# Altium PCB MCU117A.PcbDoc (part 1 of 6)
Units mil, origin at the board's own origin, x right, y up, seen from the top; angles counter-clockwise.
Board outline 2300 x 6749.64 mil, 6 copper layers (Top Signal, GND, Middle Signal, PWR, GND2, Bottom Signal), stack 61.64 mil thick; 424 components, 343 nets, 1563 pads, 921 vias.
Unrouted connection lines stored in the file: 4.
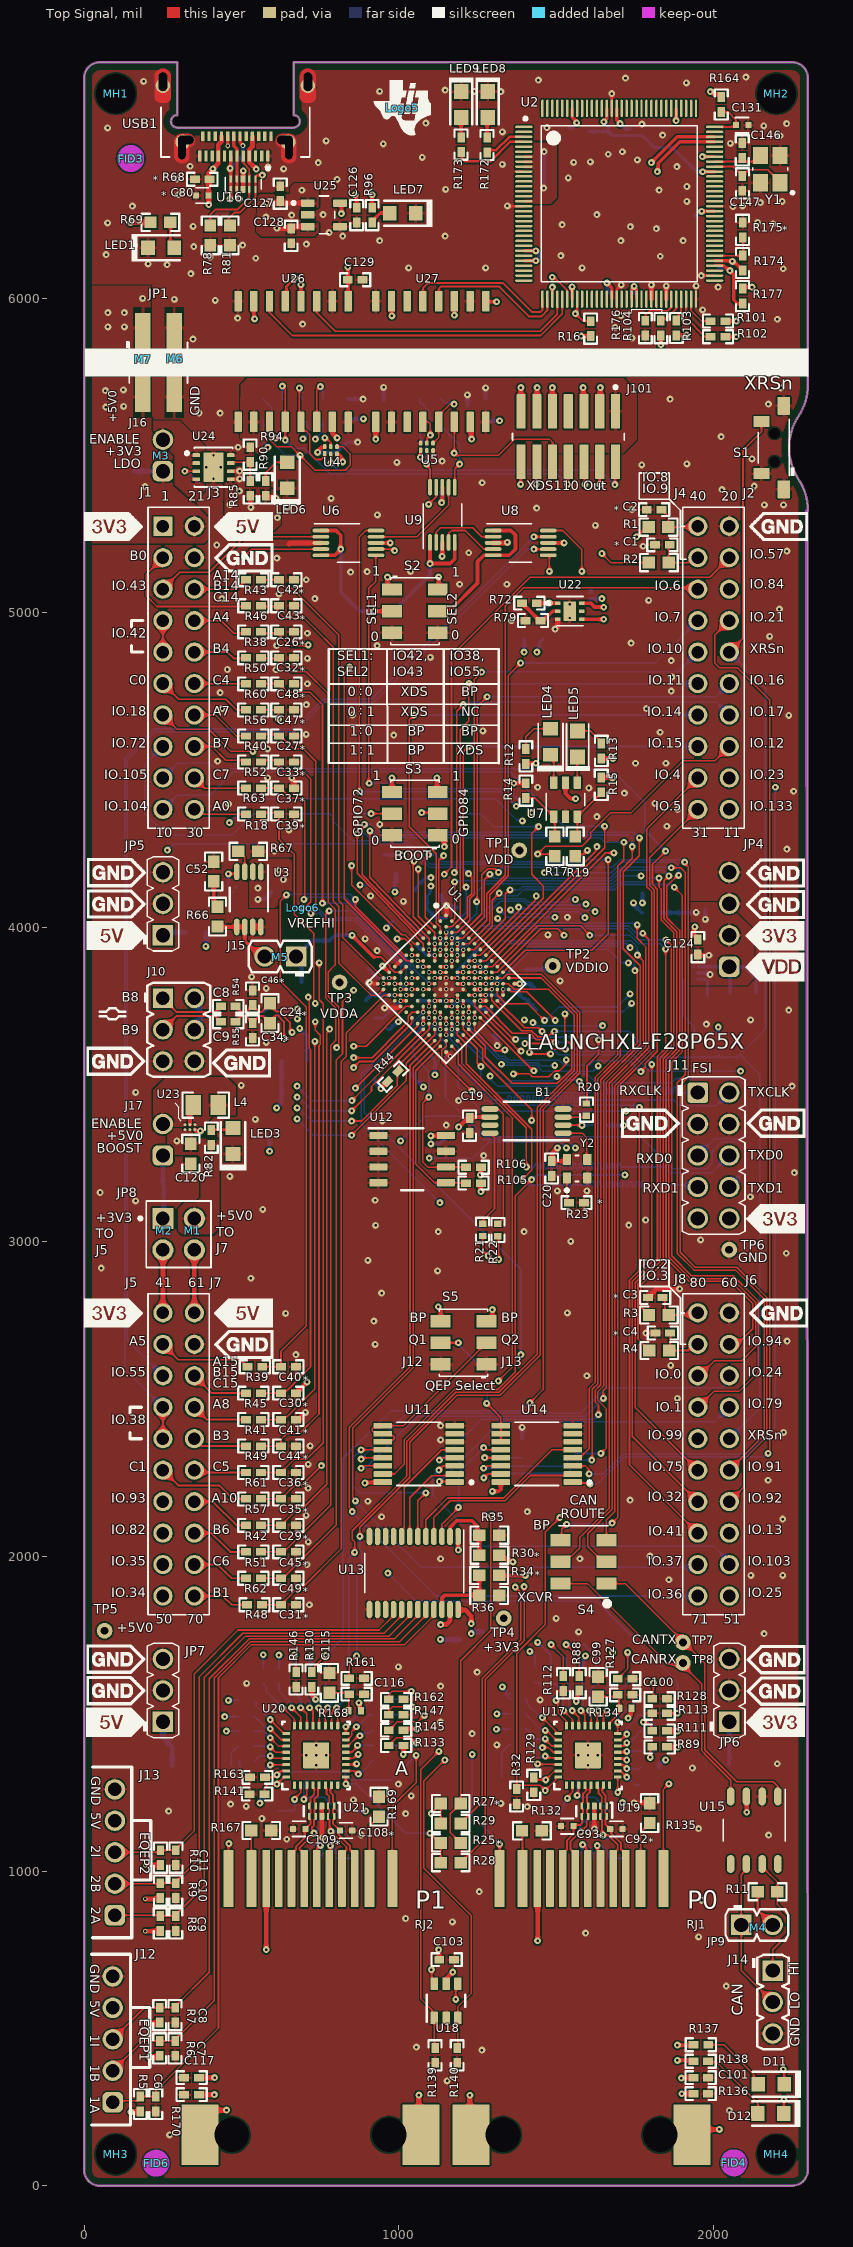
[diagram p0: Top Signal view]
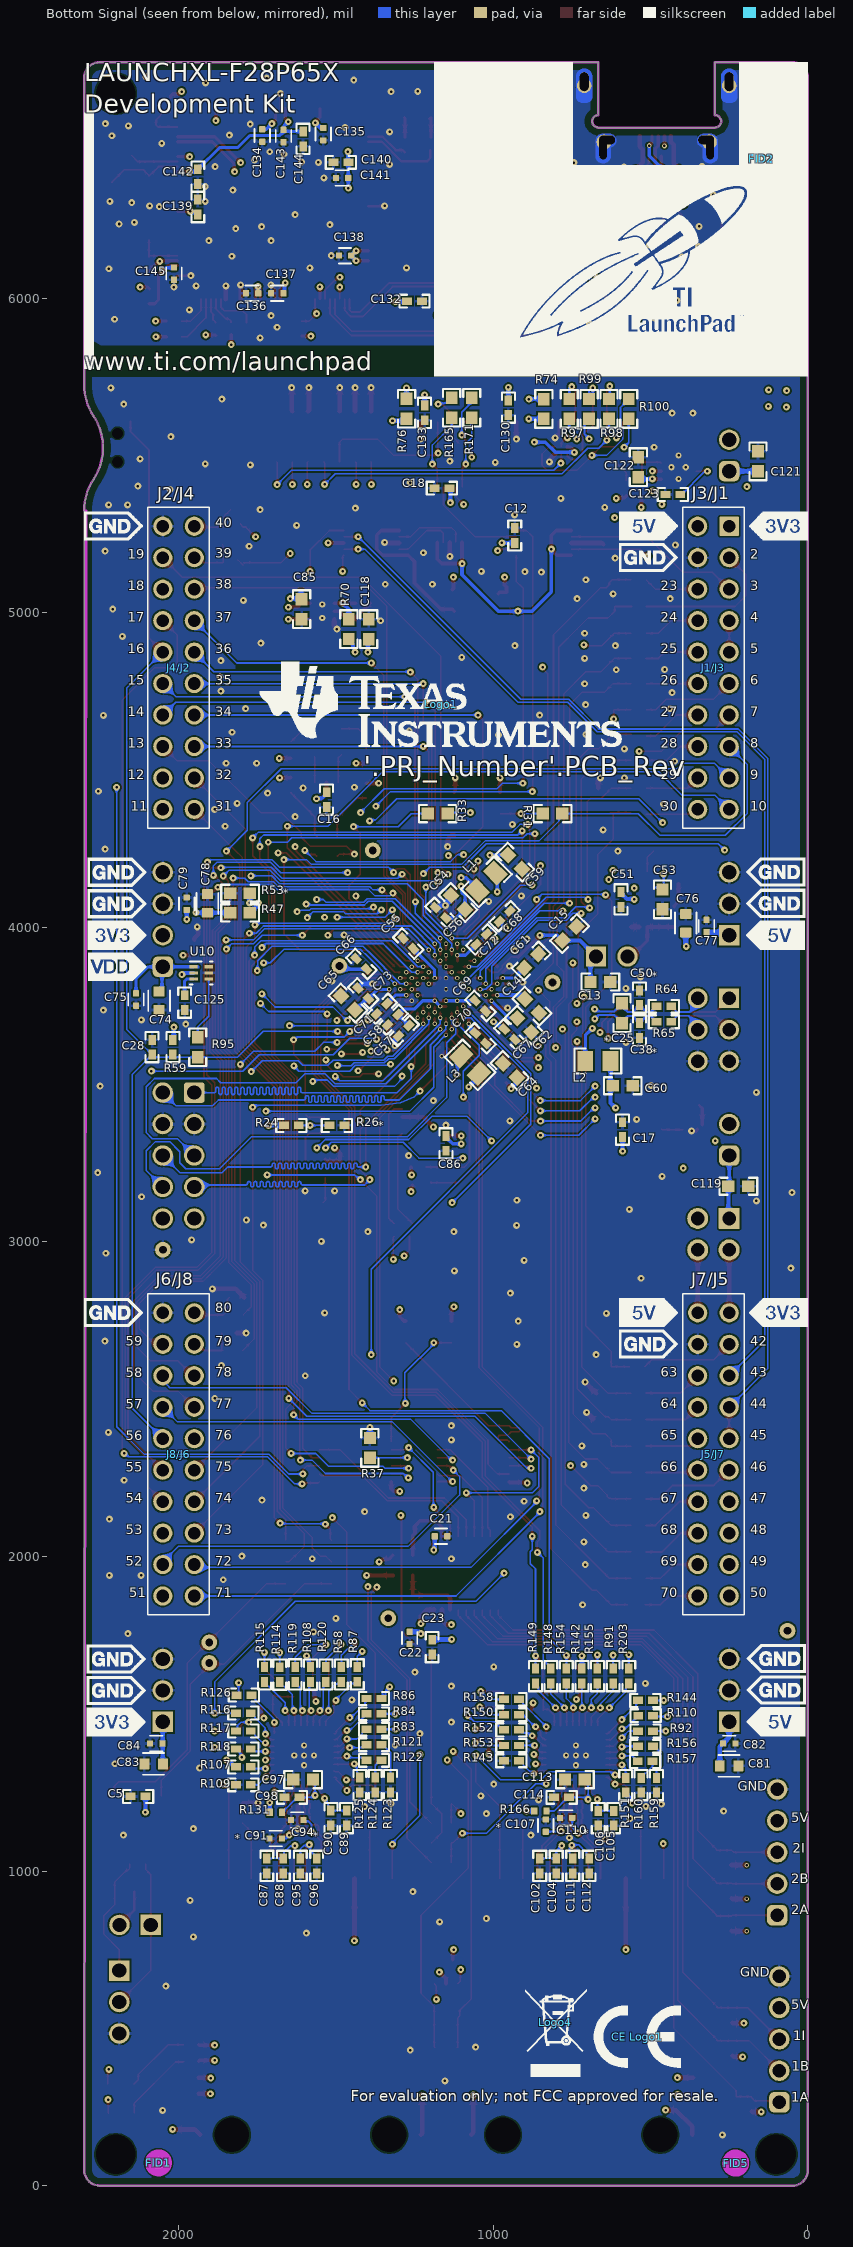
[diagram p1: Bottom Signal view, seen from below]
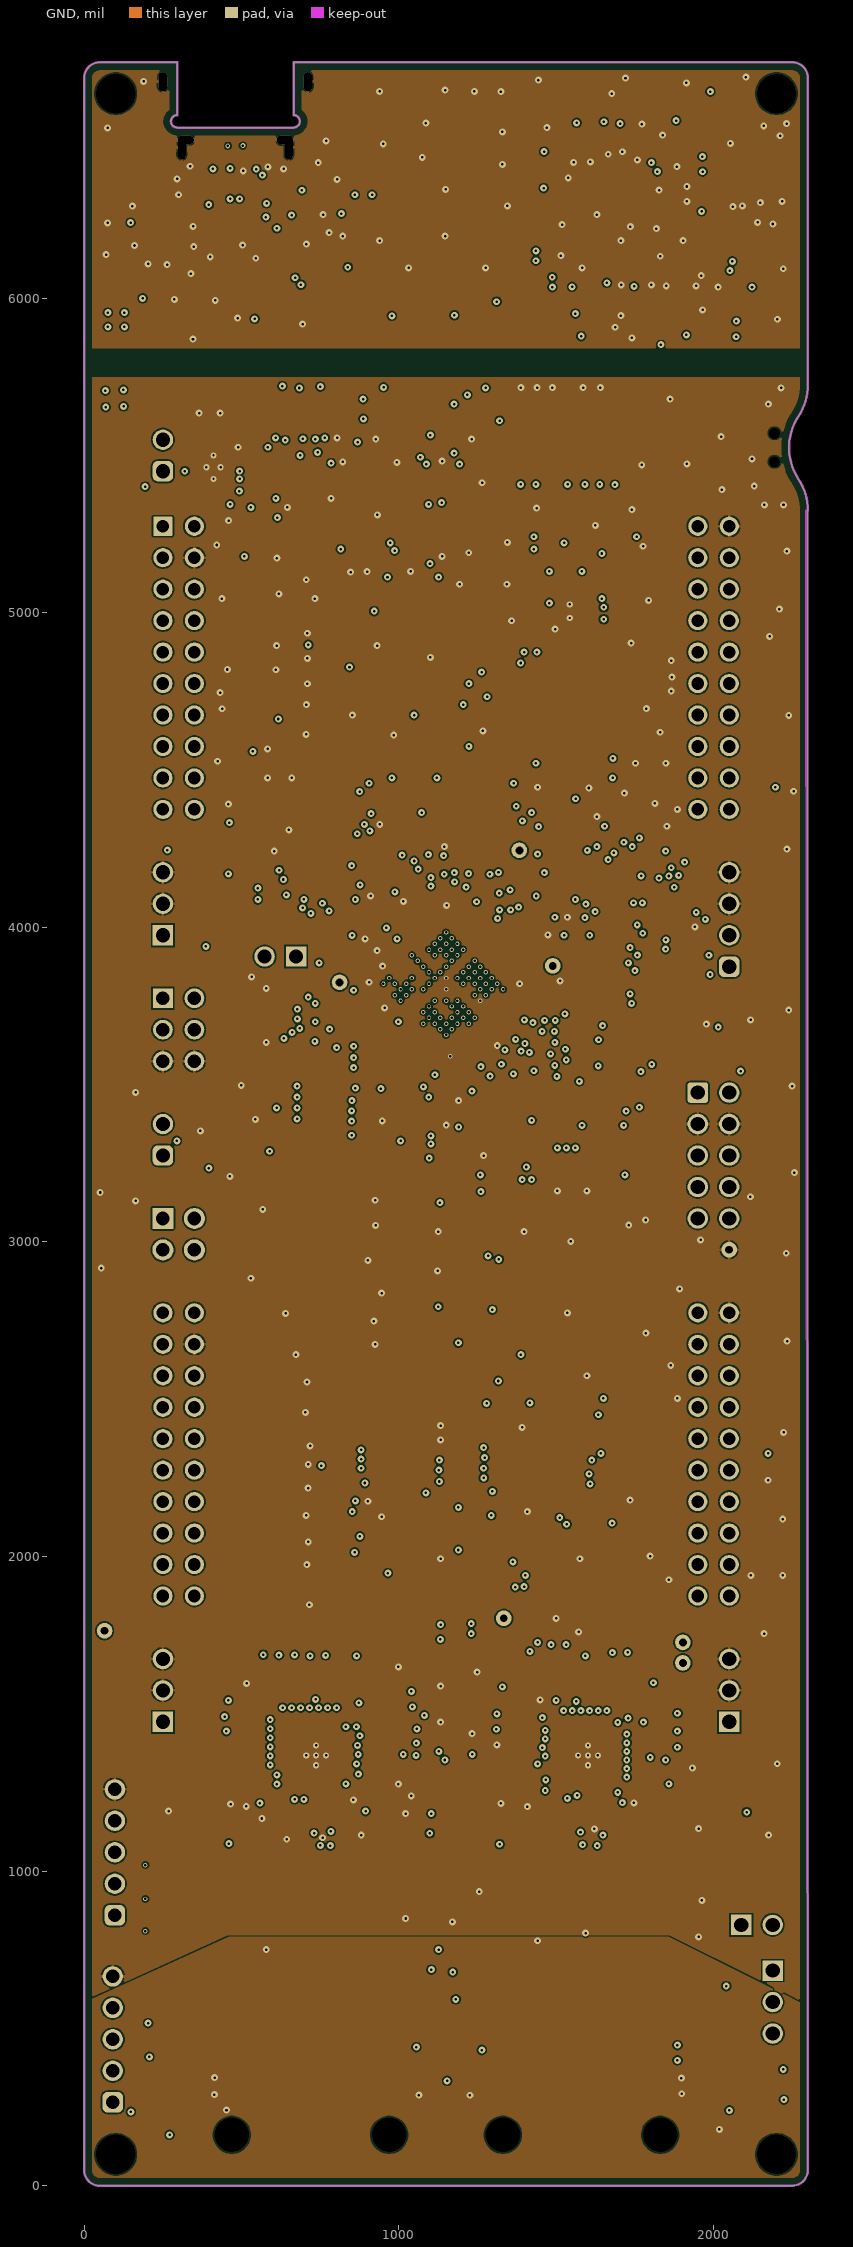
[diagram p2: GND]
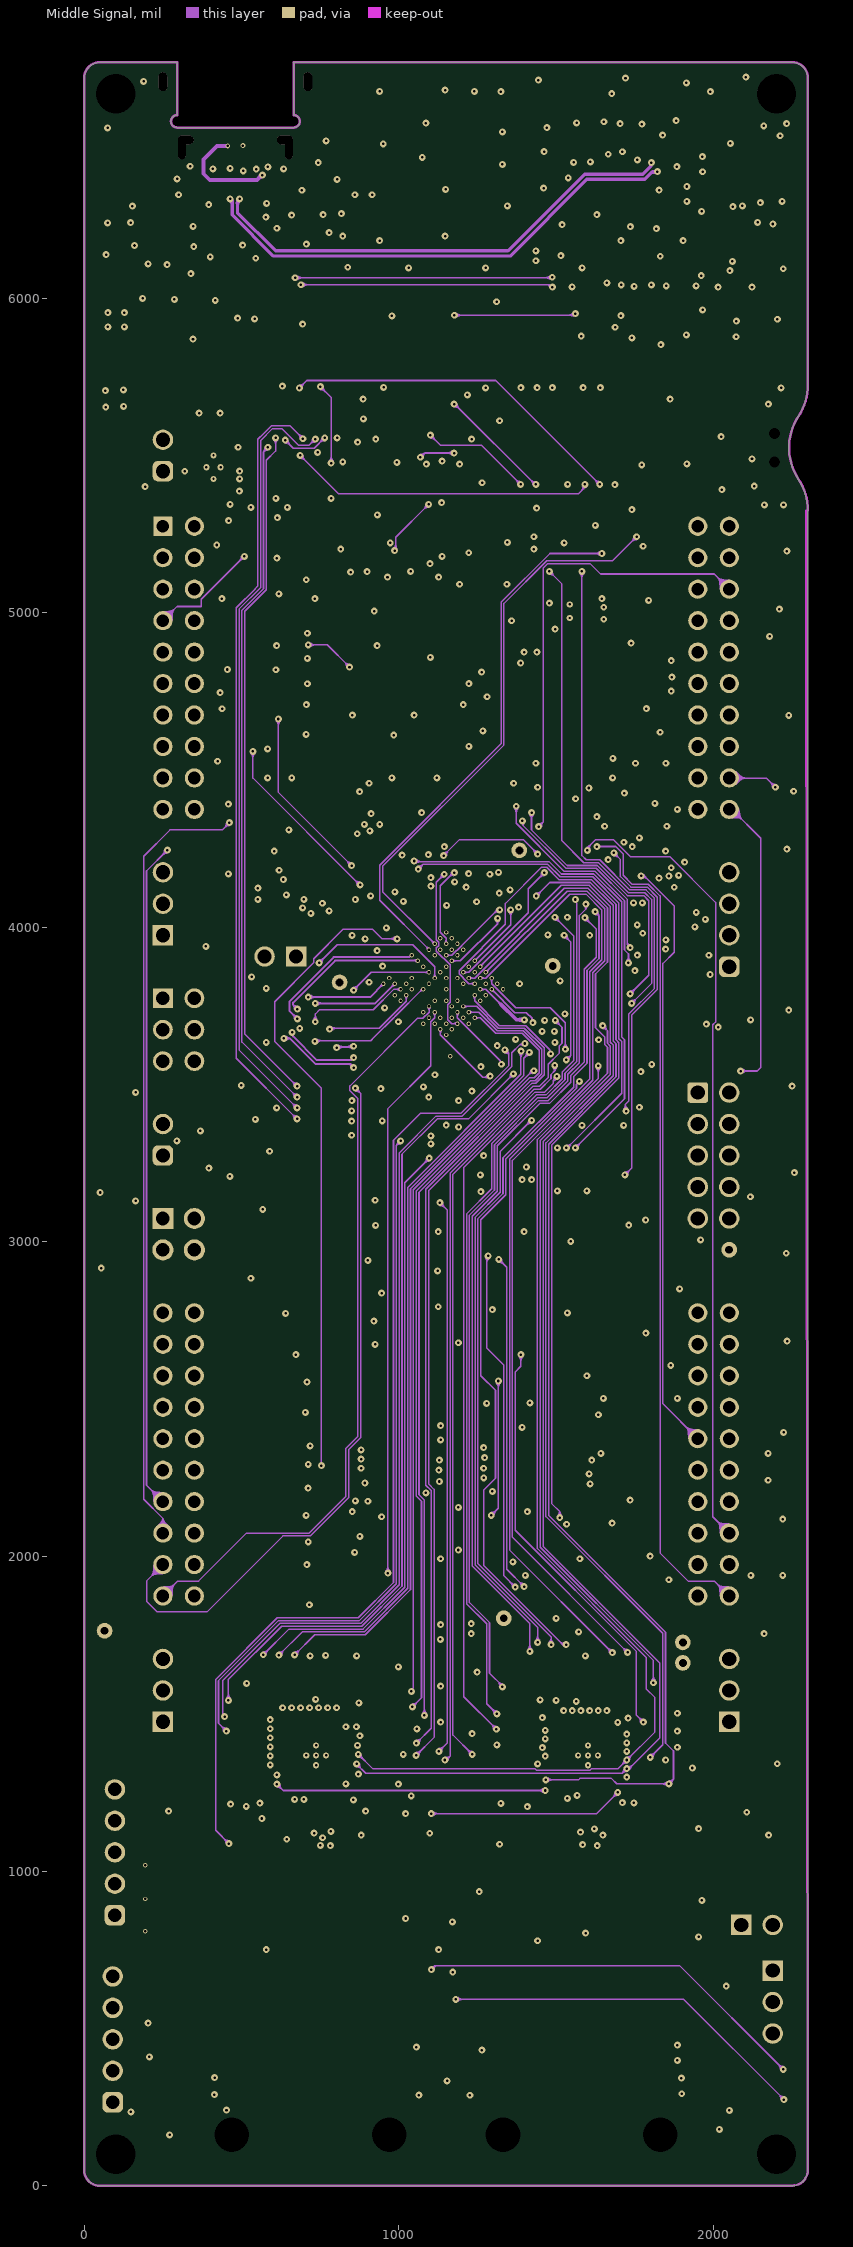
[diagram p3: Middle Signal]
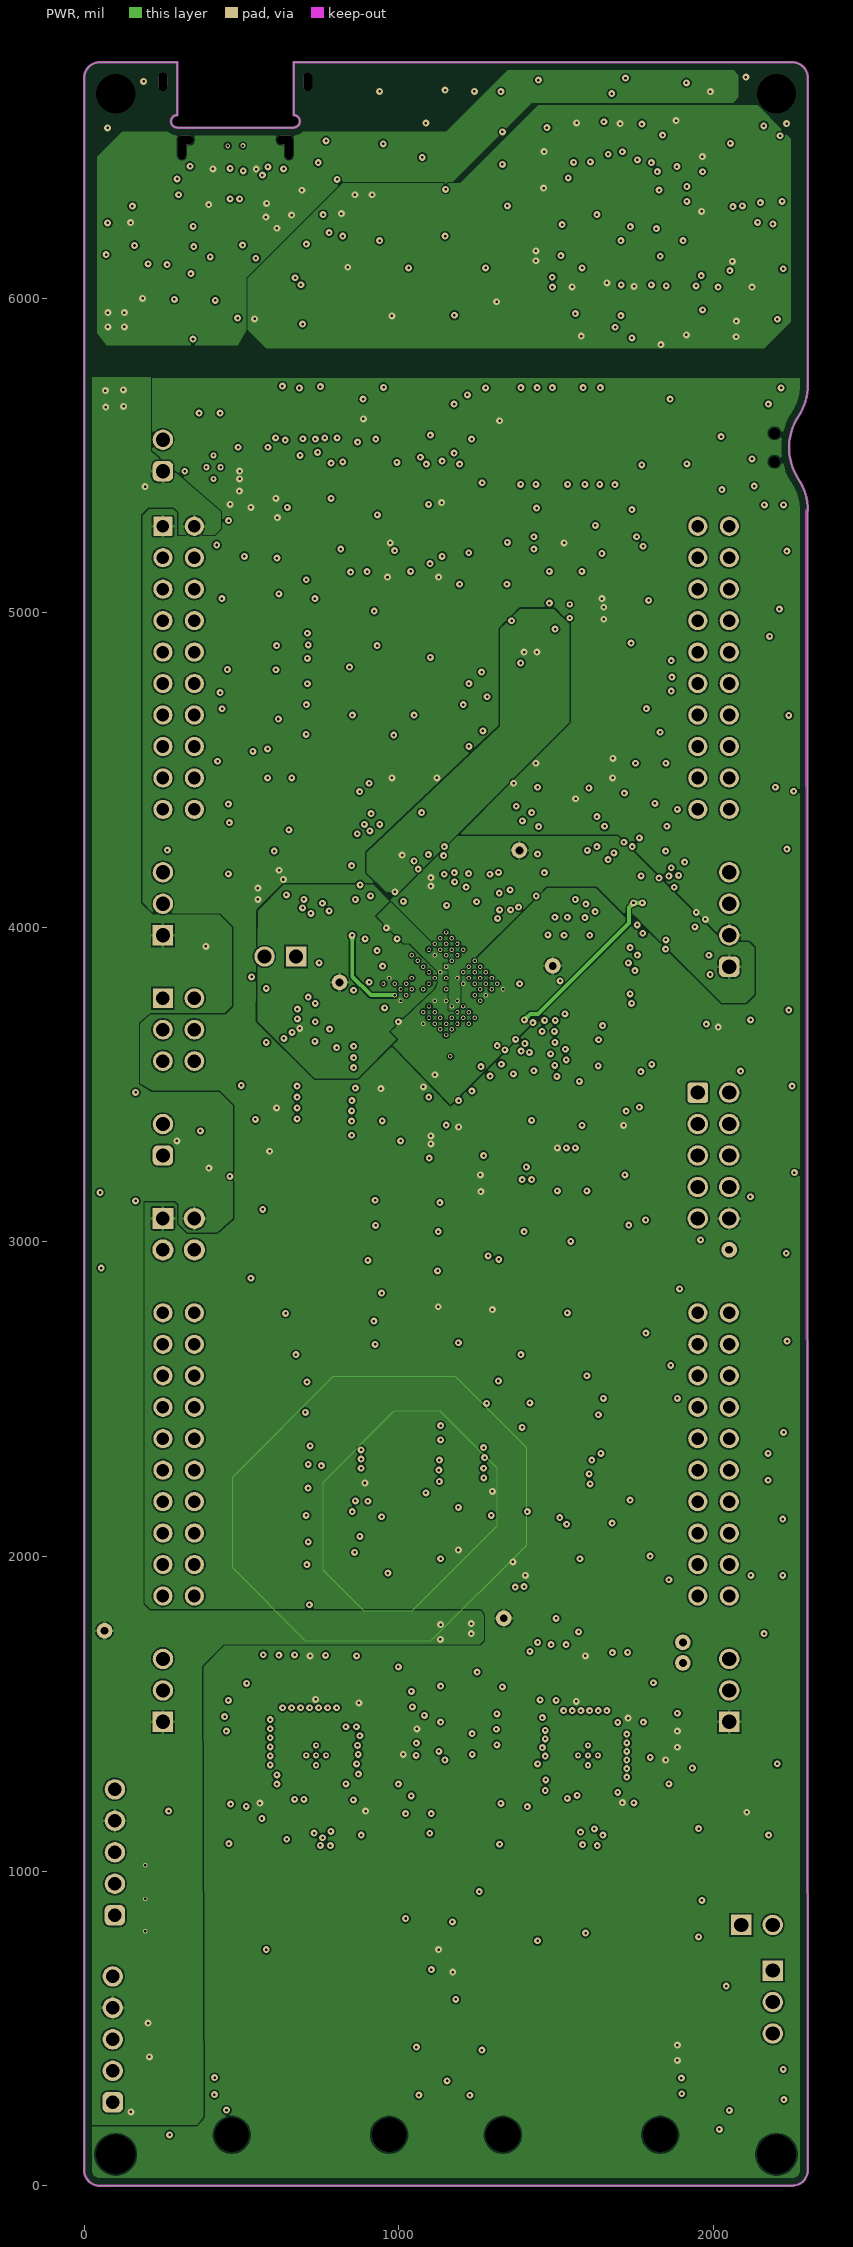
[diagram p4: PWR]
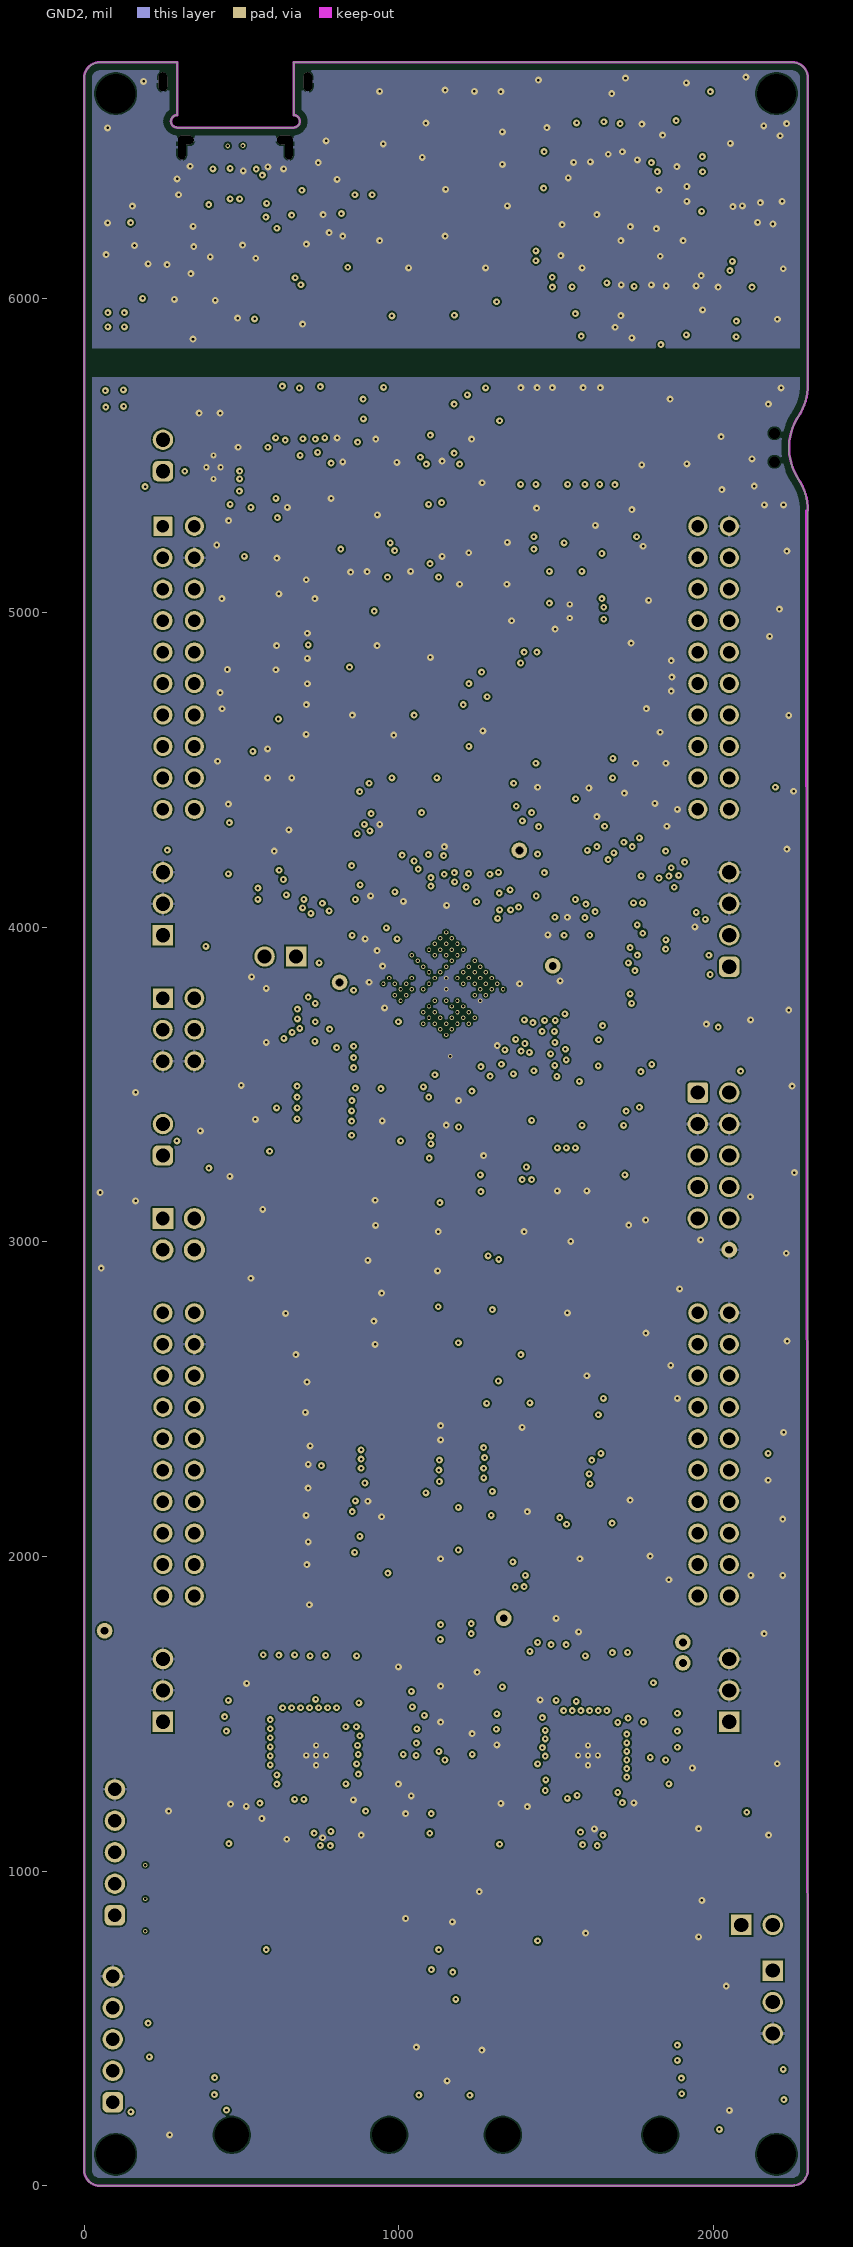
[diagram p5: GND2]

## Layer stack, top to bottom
Top Solder: solder mask 0.4, Solder Resist, Dk 3.5
Top Signal: signal copper 1.4
Dielectric 1: prepreg 6.25, FR-4, Dk 4.2
GND: signal copper 1.4
Dielectric 2: core 16.1, FR-4, Dk 4.2
Middle Signal: signal copper 1.4
Dielectric 3: prepreg 8.54, FR-4, Dk 4.2
PWR: signal copper 1.4
Dielectric 4: core 16.1, FR-4, Dk 4.2
GND2: signal copper 1.4
Dielectric 5: prepreg 6.25, FR-4, Dk 4.2
Bottom Signal: signal copper 1.4
Bottom Solder: solder mask 0.4, Solder Resist, Dk 3.5

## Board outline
49.64,0 cw(c49.64,50) -0.36,50 -0.36,6699 cw(c49.64,6699) 49.64,6749 294.91,6749 295.27,6749.64 295.27,6581.14 ccw(c295.27,6561.46) 275.58,6561.46 ccw(c295.27,6561.46) 295.27,6541.77 665.35,6541.77 ccw(c665.35,6561.46) 685.03,6561.46 ccw(c665.35,6561.46) 665.35,6581.14 665.35,6749.64 664.99,6749 2249.64,6749 cw(c2249.64,6699) 2299.64,6699 2299.64,5724 cw(c2117.97,5724) 2269.64,5624 ccw(c2421.3,5524) 2269.64,5424 cw(c2117.97,5324) 2299.64,5324 2299.64,50 cw(c2249.64,50) 2249.64,0

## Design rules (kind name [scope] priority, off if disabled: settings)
AcuteAngle [All] p1: minimum=4.50000000000000E+0001 checktracksonly=TRUE
AcuteAngle AcuteAngle_poly [InPolygon] p2: minimum=4.50000000000000E+0001 checktracksonly=FALSE
AssemblyTestPointUsage [All] p1: valid=2
BoardOutlineClearance BoardOutlineClearance_USB1 [InComponent('USB1')] p1: gap=0 ignorepadtopadclearanceinfootprint=FALSE
BoardOutlineClearance BoardOutlineClearance_MountingHoles [OnCopper and InComponentClass('Mounting Holes')] p2: gap=40 ignorepadtopadclearanceinfootprint=FALSE
BoardOutlineClearance BoardOutlineClearance_Poly [OnCopper and IsPoly] p3: gap=25 ignorepadtopadclearanceinfootprint=FALSE
BoardOutlineClearance [OnCopper and Not InComponentClass('Logo') and not InComponentClass('FiducialMark') and not InRegion(1000,500,4000,800) and not InPoly] p4: gap=10 ignorepadtopadclearanceinfootprint=FALSE
Clearance Poly [InPolygon] p1: gap=5 ignorepadtopadclearanceinfootprint=FALSE
Clearance "RJ45 pad" [InComponent('RJ1') OR InComponent('RJ2')] p2: gap=5 ignorepadtopadclearanceinfootprint=TRUE except(0: SMDPad-THPad)
Clearance Keepout [((IsTrack Or IsArc) And Not InPoly) And IsFree and IsKeepOut vs ((IsTrack Or IsArc) And Not InPoly) And IsFree and IsKeepOut] p3: gap=5 ignorepadtopadclearanceinfootprint=FALSE
Clearance USB1 [InComponent('USB1') vs OnLayer('Keep-Out Layer')] p4: gap=7.87 ignorepadtopadclearanceinfootprint=FALSE
Clearance ISVIA [ISVIA vs ISVIA] p5: gap=0.2 ignorepadtopadclearanceinfootprint=FALSE
Clearance Clearance_FiducialMark [IsKeepOut and InComponentClass('FiducialMark') vs IsPad and InComponentClass('FiducialMark')] p6: gap=0 ignorepadtopadclearanceinfootprint=FALSE
Clearance Clearance_Boardedge [All vs IsKeepOut] p7: gap=11.81 ignorepadtopadclearanceinfootprint=FALSE
Clearance INPOLYGON [InPolygon] p8: gap=11.91 ignorepadtopadclearanceinfootprint=FALSE
Clearance [All] p9: gap=5 ignorepadtopadclearanceinfootprint=FALSE except(3.7: Arc-Via Track-Via; 4: Arc-Arc Arc-Track Arc-SMDPad Track-Track Track-SMDPad)
ComponentClearance "ComponentClearance_overlay to overlay" [OnBottomSilkscreen vs OnTopSilkscreen] p1: gap=0 collisioncheckmode=3 verticalgap=0 showdistances=FALSE
ComponentClearance ComponentClearance_MountingHoles_FiducialMarks [InComponentClass('Mounting Holes') vs InComponentClass('FiducialMark')] p2: gap=10 collisioncheckmode=3 verticalgap=10 showdistances=FALSE
ComponentClearance ComponentClearance_Shunt [InComponentClass('Header') vs InComponentClass('Shunt')] p3: gap=0 collisioncheckmode=3 verticalgap=0 showdistances=FALSE
ComponentClearance ComponentClearance_Logo [InComponentClass('Logo')] p4: gap=10 collisioncheckmode=3 verticalgap=10 showdistances=FALSE
ComponentClearance ComponentClearance_ScrewToNut [(HasFootprint('NY PMS 440 0025 PH')) vs (HasFootprint('Keystone_1902C'))] p5: gap=5 collisioncheckmode=3 verticalgap=10 showdistances=FALSE
ComponentClearance ComponentClearance_MountingHoles [InComponentClass('Mounting Holes')] p6 off: gap=250 collisioncheckmode=3 verticalgap=100000 showdistances=FALSE
ComponentClearance ComponentClearance_SmallPassives [HasFootprint('0201*') or HasFootprint('0402*') or HasFootprint('0508') or HasFootprint('0603*') or HasFootprint('0612') or HasFootprint('0805*') or HasFootprint('0815*') or HasFootprint('0830*') or HasFootprint('1206*') or HasFootprint('1210*') or HasFootprint('1808*') or HasFootprint('1812*') or HasFootprint('1825*') or HasFootprint('2010*') or HasFootprint('2220*') or HasFootprint('2225*') or HasFootprint('2512*') or HasFootprint('2728*') or HasFootprint('3518*') vs HasFootprint('0201*') or HasFootprint('0402*') or HasFootprint('0508') or HasFootprint('0603*') or HasFootprint('0612') or HasFootprint('0805*') or HasFootprint('0815*') or HasFootprint('0830*') or HasFootprint('1206*') or HasFootprint('1210*') or HasFootprint('1808*') or HasFootprint('1812*') or HasFootprint('1825*') or HasFootprint('2010*') or HasFootprint('2220*') or HasFootprint('2225*') or HasFootprint('2512*') or HasFootprint('2728*') or HasFootprint('3518*')] p7 off: gap=10 collisioncheckmode=3 verticalgap=0 showdistances=FALSE
ComponentClearance ComponentClearance_THtoSMT [IsThruComponent vs IsSMTComponent] p8 off: gap=30 collisioncheckmode=3 verticalgap=30 showdistances=FALSE
ComponentClearance ComponentClearance_THtoTH [IsThruComponent vs IsThruComponent] p9 off: gap=30 collisioncheckmode=3 verticalgap=30 showdistances=FALSE
DiffPairsRouting USB_DiffPairsRouting_90 [InDifferentialPairClass('All Differential Pairs')] p1: maxlimit=100 minlimit=5 mostfreqgap=6 toplayer_minwidth=4 toplayer_maxwidth=15 toplayer_prefwidth=6.1 midlayer1_minwidth=6 midlayer1_maxwidth=15 midlayer1_prefwidth=6.1 midlayer2_minwidth=6 midlayer2_maxwidth=15 midlayer2_prefwidth=6.1 midlayer3_minwidth=6 midlayer3_maxwidth=15 midlayer3_prefwidth=6.1 midlayer4_minwidth=6 midlayer4_maxwidth=15 midlayer4_prefwidth=6.1 bottomlayer_minwidth=4 bottomlayer_maxwidth=15 bottomlayer_prefwidth=6.1 maxuncoupledlength=1000
DiffPairsRouting [All] p2: maxlimit=10 minlimit=6 mostfreqgap=6 toplayer_minwidth=4 toplayer_maxwidth=6.2 toplayer_prefwidth=4.9 midlayer1_minwidth=4.9 midlayer1_maxwidth=6.2 midlayer1_prefwidth=4.9 midlayer2_minwidth=4.9 midlayer2_maxwidth=15 midlayer2_prefwidth=4.9 midlayer3_minwidth=4.9 midlayer3_maxwidth=15 midlayer3_prefwidth=4.9 midlayer4_minwidth=4.9 midlayer4_maxwidth=15 midlayer4_prefwidth=4.9 bottomlayer_minwidth=4 bottomlayer_maxwidth=6.2 bottomlayer_prefwidth=4.9 maxuncoupledlength=500
FabricationTestPointUsage TestPointUsage [All] p1: valid=2 allowmultiple=FALSE
FabricationTestpoint Testpoint [All] p1: side=3 testpointundercomponent=TRUE minsize=40 maxsize=100 preferedsize=60 minholesize=0 maxholesize=40 preferedholesize=32 testpointgrid=1 allowsidetop=TRUE allowsidebottom=TRUE usegrid=TRUE gridtolerance=0.01
FanoutControl Fanout_LCC [IsLCC] p1: bgadir=Out bgaviamode=Centered fanoutstyle=Auto fanoutdirection=Alternating viagrid=1 // Fanout_LCC (Default Rule)
FanoutControl Fanout_BGA [IsBGA] p2: bgadir=Out bgaviamode=Centered fanoutstyle=Auto fanoutdirection=Alternating viagrid=1 // Fanout_BGA (Default Rule)
FanoutControl Fanout_Default [All] p4: bgadir=Out bgaviamode=Centered fanoutstyle=Auto fanoutdirection=Alternating viagrid=1 // Fanout_Default (Default Rule)
FanoutControl Fanout_Small [(CompPinCount < 5)] p5: bgadir=Out bgaviamode=Centered fanoutstyle=Auto fanoutdirection=OutThenIn viagrid=1 // Fanout_Small (Default Rule)
HoleSize [All] p1: absolutevalues=TRUE maxlimit=251 minlimit=7.87 maxpercent=80.000 minpercent=20.000
HoleToHoleClearance HoleToHoleClearance_USB1 [InComponent('USB1') vs InComponent('USB1')] p1: gap=0 allowstackedmicrovias=TRUE
HoleToHoleClearance [All] p2: gap=10 allowstackedmicrovias=TRUE
MatchedLengths FSIRX [InNetClass('FSIRX')] p1: tolerance=25 checknetsindiffpair=FALSE checkdiffpairvsdiffpair=TRUE checkxsignals=TRUE checkothers=TRUE
MatchedLengths FSITX [InNetClass('FSITX')] p2: tolerance=25 checknetsindiffpair=FALSE checkdiffpairvsdiffpair=TRUE checkxsignals=TRUE checkothers=TRUE
MinimumAnnularRing MinimumAnnularRing_ThermalPadVias [IsVia and InAnyComponent] p1: minimumring=3
MinimumAnnularRing MinimumAnnularRing_usb1 [InComponent('USB1')] p2: minimumring=0
MinimumAnnularRing [All] p3: minimumring=3
MinimumSolderMaskSliver MinimumSolderMaskSliver_Logo [InComponentClass('Logo') vs InComponentClass('Logo')] p1: minsoldermaskwidth=0.7
MinimumSolderMaskSliver [All] p2: minsoldermaskwidth=3
PlaneClearance PlaneClearance_Via [IsVia] p1: clearance=10
PlaneClearance [All] p2: clearance=10
PlaneConnect [All] p1: planeconnectstyle=Relief reliefexpansion=10 reliefentries=4 reliefconductorwidth=25 reliefairgap=10
PolygonConnect PolygonConnect_via [IsVia] p1: connectstyle=Direct reliefconductorwidth=10 reliefentries=4 polygonreliefangle="90 Angle" airgapwidth=10
PolygonConnect PolygonConnect_GND_under_device [Name = 'TOP_SIGNAL_GND_P125'] p2: connectstyle=Direct reliefconductorwidth=10 reliefentries=4 polygonreliefangle="90 Angle" airgapwidth=5
PolygonConnect PolygonConnect_via_VDD [Name = 'PWR_VDD_P012'] p3: thpad.connectstyle=Relief thpad.reliefconductorwidth=10 thpad.reliefentries=4 thpad.polygonreliefangle="90 Angle" thpad.airgapwidth=5 smdpad.connectstyle=Relief smdpad.reliefconductorwidth=10 smdpad.reliefentries=4 smdpad.polygonreliefangle="90 Angle" smdpad.airgapwidth=5 via.connectstyle=Direct via.reliefconductorwidth=10 via.reliefentries=4 via.polygonreliefangle="90 Angle" via.airgapwidth=5
PolygonConnect PolygonConnect_via_VDDIO [Name = 'PWR_VDDIO_P129'] p4: thpad.connectstyle=Relief thpad.reliefconductorwidth=10 thpad.reliefentries=4 thpad.polygonreliefangle="90 Angle" thpad.airgapwidth=5 smdpad.connectstyle=Relief smdpad.reliefconductorwidth=10 smdpad.reliefentries=4 smdpad.polygonreliefangle="90 Angle" smdpad.airgapwidth=5 via.connectstyle=Direct via.reliefconductorwidth=10 via.reliefentries=4 via.polygonreliefangle="90 Angle" via.airgapwidth=5
PolygonConnect [All] p5: connectstyle=Relief reliefconductorwidth=10 reliefentries=4 polygonreliefangle="90 Angle" airgapwidth=5
RoutingVias ThermalPadVias [IsVia and InAnyComponent] p1: holewidth=8 width=22 viastyle="Through Hole" minholewidth=7.87 minwidth=14 maxholewidth=8 maxwidth=22
RoutingVias [All] p2: holewidth=8 width=22 viastyle="Through Hole" minholewidth=7.87 minwidth=14 maxholewidth=8 maxwidth=22
ShortCircuit ShortCircuit_RJ45 [InComponent('RJ1') And IsThruPin Or InComponent('RJ2') And IsThruPin] p1: allowed=TRUE
ShortCircuit [All] p2: allowed=FALSE
SilkToBoardRegionClearance [Not ((IsComment or IsDesignator) And (Hide <> 'False')) and not InRegion(1000,500,4000,800)] p1:
SilkToSilkClearance SilkToSilkClearance_Pb-FreeLogo [(HasFootprint('Pb-Free_Overlay_Medium') OR HasFootprint('Pb-Free_Overlay_Small')) vs (HasFootprint('Pb-Free_Overlay_Medium') OR HasFootprint('Pb-Free_Overlay_Small'))] p1: silktosilkclearance=0
SilkToSilkClearance [All] p2: silktosilkclearance=3
SilkToSolderMaskClearance SilkToComponentPadClearance [(IsPad or IsFill or IsRegion) and InAnycomponent] p1: minsilkscreentomaskgap=3 clearancetoexposedcopper=TRUE
SilkToSolderMaskClearance "Silk to Solder Mask Opening" [All] p2: minsilkscreentomaskgap=3 clearancetoexposedcopper=TRUE
SolderMaskExpansion [All] p1: expansion=1.97 istentingtop=FALSE
UnRoutedNet [All] p1: checkbadconnections=TRUE
Width USB_width [InNetClass('Analog')] p1: maxlimit=6.1 minlimit=4 preferedwidth=6
Width [All] p2: maxlimit=15 minlimit=4 preferedwidth=5 checkconnectedcopper=TRUE
11 further rules are at their usual default settings.

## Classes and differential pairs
component class MCU117A_F28P65X_Device: C28 C54 C55 C56 C57 C58 C59 C60 C61 C62 C64 C65 C66 C67 C68 C69 C70 C71 C72 C73 L1 L2 L3 R44 R47 R53 R59 S1
component class MCU117A_XDS110_MCU: C129 C130 C131 C132 C133 C134 C135 C136 C137 C138 C139 C140 C141 C142 C143 C144 C145 C146 C147 J101 LED8 LED9 R16 R74 R76 R97 R98 R99 R100 R101 R102 R103 R104 R164 R165 R171 R172 R173 R174 R175 R176 R177 U2 U4 U5 U26 U27 Y1
component class MCU117A_EtherCAT: C86 C87 C88 C89 C90 C91 C92 C93 C94 C95 C96 C97 C98 C99 C100 C101 C102 C103 C104 C105 C106 C107 C108 C109 C110 C111 C112 C113 C114 C115 C116 C117 D11 D12 R32 R58 R83 R84 R86 R87 R88 R89 R91 R92 R105 R106 R107 R108 R109 R110 R111 R112 R113 R114 R115 R116 R117 R118 R119 R120 R121 R122 R123 R124 R125 R126 R127 R128 R129 R130 R131 R132 R133 R134 R135 R136 R137 R138 R139 R140 R141 R142 R143 R144 R145 R146 R147 R148 R149 R150 R151 R152 R153 R154 R155 R156 R157 R158 R159 R160 R161 R162 R163 R166 R167 R168 R169 R170 R203 RJ1 RJ2 U12 U17 U18 U19 U20 U21
net class FSITX: GPIO49_FSITXD0 GPIO50_FSITXD1 GPIO51_FSITXCLK
net class FSIRX: GPIO52_FSIRXD0 GPIO53_FSIRXD1 GPIO54_FSIRXCLK
component class MCU117A_USB_and_Power: C74 C75 C76 C77 C78 C79 C80 C81 C82 C83 C84 C85 C118 C119 C120 C121 C122 C123 C124 C125 C126 C127 C128 J16 J17 JP1 JP4 JP5 JP6 JP7 JP10 L4 LED1 LED3 LED6 LED7 M5 M6 M7 R68 R69 R70 R72 R78 R79 R81 R82 R85 R90 R94 R95 R96 TP1 TP2 TP3 TP4 TP5 TP6 U10 U16 U22 U23 U24 U25 USB1
component class MCU117A_ADC: C13 C14 C15 C24 C25 C26 C27 C29 C30 C31 C32 C33 C34 C35 C36 C37 C38 C39 C40 C41 C42 C43 C44 C45 C46 C47 C48 C49 C50 C51 C52 C53 J15 M4 R18 R38 R39 R40 R41 R42 R43 R45 R46 R48 R49 R50 R51 R52 R54 R55 R56 R57 R60 R61 R62 R63 R64 R65 R66 R67 R? U1 U3
component class MCU117A_Connectors: C1 C2 C3 C4 C5 C6 C7 C8 C9 C10 C11 J1/J3 J4/J2 J5/J7 J8/J6 J10 J11 J12 J13 J14 JP8 JP9 M1 M2 M3 R1 R2 R3 R4 R5 R6 R7 R8 R9 R10 R11 TP7 TP8 U15
component class MCU117A_AltRouting_Misc: B1 C12 C16 C17 C18 C19 C20 C21 C22 C23 LED4 LED5 R12 R13 R14 R15 R17 R19 R20 R21 R22 R23 R24 R25 R26 R27 R28 R29 R30 R31 R33 R34 R35 R36 R37 S2 S3 S4 S5 U6 U7 U8 U9 U11 U13 U14 Y2
component class Header: J10 J11 J12 J13 J14 J15 J16 J17 JP1 JP4 JP5 JP6 JP7 JP9 JP10
component class AssemblyNote: ZZ1 ZZ2 ZZ3
component class FiducialMark: FID1 FID2 FID3 FID4 FID5 FID6
component class MCU117A_Hardware: "CE Logo1" FID1 FID2 FID3 FID4 FID5 FID6 Logo1 Logo3 Logo4 Logo5 Logo6 MH1 MH2 MH3 MH4 ZZ1 ZZ2 ZZ3
component class Logo: Logo1 Logo5 Logo6
component class Shunt: M1 M2 M3 M4 M5 M6 M7
differential pair MCU_C8C9: +MCU_C8C9_P -MCU_C8C9_N
differential pair ADCINC8C9: +ADCINC8C9_P -ADCINC8C9_N
differential pair MCU_B8B9: +MCU_B8B9_P -MCU_B8B9_N
differential pair USB_D: +USB_D_P -USB_D_N
differential pair ADCINB8B9: +ADCINB8B9_P -ADCINB8B9_N
differential pair PHY1_TD: +PHY1_TD_P -PHY1_TD_N
differential pair PHY1_RD: +PHY1_RD_P -PHY1_RD_N
differential pair PHY0_TD: +PHY0_TD_P -PHY0_TD_N
differential pair PHY0_RD: +PHY0_RD_P -PHY0_RD_N

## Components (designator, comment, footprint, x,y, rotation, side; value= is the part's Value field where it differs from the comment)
B1 "LMK1C1104PW" PW0008A_N 1405.4,3384.12 r180 top
C1 "885012205037" 0402 1837.29,5215.41 r180 top value=0.1uF
C2 "885012205037" 0402 1811.33,5327.3 r180 top value=0.1uF
C3 "885012205037" 0402 1814.69,2823.34 r180 top value=0.1uF
C4 "885012205037" 0402 1838.61,2710.54 r180 top value=0.1uF
C5 "885012205037" 0402 2128.56,1237.59 r180 bottom value=0.1uF
C6 "885012205061" 0402 227.35,260 r270 top value=1000pF
C7 "885012205061" 0402 288.63,437.1 r270 top value=1000pF
C8 "885012205061" 0402 288.63,542.43 r270 top value=1000pF
C9 "885012205061" 0402 290.65,834 r270 top value=1000pF
C10 "885012205061" 0402 290.81,938 r270 top value=1000pF
C11 "885012205061" 0402 291.31,1043.05 r270 top value=1000pF
C12 "885012205037" 0402 931.57,5245.29 r270 bottom value=0.1uF
C13 "GRM188R61C475KAAJ" 0603 659.33,3826.06 r180 bottom value=4.7uF
C14 "GRM188R61C475KAAJ" 0603 876.64,3749.54 r225 bottom value=4.7uF
C15 "GRM188R61C475KAAJ" 0603 757.13,3980.05 r135 bottom value=4.7uF
C16 "885012205037" 0402 1529.55,4405.67 r270 bottom value=0.1uF
C17 "885012205037" 0402 589.08,3356.65 r270 bottom value=0.1uF
C18 "885012205037" 0402 1162.91,5395.64 r0 bottom value=0.1uF
C19 "885012205037" 0402 1224.61,3369.78 r270 top value=0.1uF
C20 "885012205037" 0402 1485.31,3233.33 r270 top value=0.1uF
C21 "885012205018" FP-885012205018_0402-MFG 1165.93,2064.78 r180 bottom value=100nF
C22 "885012205018" FP-885012205018_0402-MFG 1265.71,1741.38 r90 bottom value=100nF
C23 "885012205061" 0402 1194,1712 r270 bottom value=1000pF
C24 "C0603C331J5GACTU" 0603 590.34,3726.93 r90 top value=330pF
C25 "C0603C331J5GACTU" 0603 590.34,3726.93 r90 bottom value=330pF
C26 "GRM1555C1H331JA01D" 0402 642.43,4939.12 r0 top value=330pF
C27 "GRM1555C1H331JA01D" 0402 642.43,4608.08 r0 top value=330pF
C28 "885012205037" 0402 2084.09,3618.79 r90 bottom value=0.1uF
C29 "GRM1555C1H331JA01D" 0402 648.92,2099.15 r0 top value=330pF
C30 "GRM1555C1H331JA01D" 0402 648.92,2519.39 r0 top value=330pF
C31 "GRM1555C1H331JA01D" 0402 648.92,1847 r0 top value=330pF
C32 "GRM1555C1H331JA01D" 0402 642.43,4856.36 r0 top value=330pF
C33 "GRM1555C1H331JA01D" 0402 642.43,4525.32 r0 top value=330pF
C34 "GRM1555C1H331JA01D" 0402 534.9,3672.39 r270 top value=330pF
C35 "GRM1555C1H331JA01D" 0402 648.92,2183.2 r0 top value=330pF
C36 "GRM1555C1H331JA01D" 0402 648.92,2267.25 r0 top value=330pF
C37 "GRM1555C1H331JA01D" 0402 642.43,4442.57 r0 top value=330pF
C38 "GRM1555C1H331JA01D" 0402 534.9,3672.39 r270 bottom value=330pF
C39 "GRM1555C1H331JA01D" 0402 642.58,4359.81 r0 top value=330pF
C40 "GRM1555C1H331JA01D" 0402 648.92,2603.44 r0 top value=330pF
C41 "GRM1555C1H331JA01D" 0402 648.92,2435.35 r0 top value=330pF
C42 "GRM1555C1H331JA01D" 0402 642.43,5104.64 r0 top value=330pF
C43 "GRM1555C1H331JA01D" 0402 642.43,5021.88 r0 top value=330pF
C44 "GRM1555C1H331JA01D" 0402 648.92,2351.3 r0 top value=330pF
C45 "GRM1555C1H331JA01D" 0402 648.92,2015.1 r0 top value=330pF
C46 "GRM1555C1H331JA01D" 0402 534.9,3776.13 r90 top value=330pF
C47 "GRM1555C1H331JA01D" 0402 642.43,4690.84 r0 top value=330pF
C48 "GRM1555C1H331JA01D" 0402 642.43,4773.6 r0 top value=330pF
C49 "GRM1555C1H331JA01D" 0402 648.92,1931.05 r0 top value=330pF
C50 "GRM1555C1H331JA01D" 0402 534.9,3776.13 r90 bottom value=330pF
C51 "885012205037" 0402 593.77,4088.75 r270 bottom value=0.1uF
C52 "GRM188R61A226ME15D" 0603 411.27,4177.33 r90 top value=22uF
C53 "GRM188R61C475KAAJ" 0603 461.88,4088.75 r270 bottom value=4.7uF
C54 "GRM188R61C106KAALD" 0603 1112.02,4079.38 r45 bottom value=10uF
C55 "885012205037" 0402 1270.21,3948.43 r45 bottom value=0.1uF
C56 "885012205037" 0402 1167.28,4046.52 r45 bottom value=0.1uF
C57 "885012205037" 0402 1284.42,3671.3 r315 bottom value=0.1uF
C58 "885012205037" 0402 1319.52,3705.92 r315 bottom value=0.1uF
C59 "GRM188R61C106KAALD" 0603 930.89,4207.39 r225 bottom value=10uF
C60 "885012106018" 0603 588.17,3496.27 r180 bottom value=2.2uF
C61 "885012106018" 0603 878.91,3893.07 r135 bottom value=2.2uF
C62 "885012106018" 0603 901.18,3688.84 r225 bottom value=2.2uF
C64 "885012106018" 0603 946.77,3545.19 r45 bottom value=2.2uF
C65 "885012106018" 0603 1461,3759.14 r45 bottom value=2.2uF
C66 "885012205037" 0402 1418.82,3883.57 r45 bottom value=0.1uF
C67 "885012205037" 0402 948.05,3659.45 r225 bottom value=0.1uF
C68 "885012205037" 0402 963.87,4035.19 r135 bottom value=0.1uF
C69 "885012205037" 0402 1040.51,3749.94 r225 bottom value=0.1uF
C70 "885012205037" 0402 1040.21,3647.35 r225 bottom value=0.1uF
C71 "885012205037" 0402 1353.98,3740.86 r315 bottom value=0.1uF
C72 "885012205037" 0402 1037.43,3961.63 r135 bottom value=0.1uF
C73 "885012205037" 0402 1412.74,3789.95 r45 bottom value=0.1uF
C74 "CC0603KRX5R6BB106" FP-CC0603KRX5R6BB106_0603-MFG 2061.95,3766.53 r90 bottom value=10µF
C75 "885012205018" FP-885012205018_0402-MFG 2135.13,3770.47 r90 bottom value=100nF
C76 "CC0603KRX5R6BB106" FP-CC0603KRX5R6BB106_0603-MFG 388,4013 r270 bottom value=10µF
C77 "885012205018" FP-885012205018_0402-MFG 322,4004 r90 bottom value=100nF
C78 "CC0603KRX5R6BB106" FP-CC0603KRX5R6BB106_0603-MFG 1908.11,4075.83 r270 bottom value=10µF
C79 "885012205018" FP-885012205018_0402-MFG 1974,4075 r90 bottom value=100nF
C80 "885012205064" FP-885012205064_0402-MFG 375.03,6325.94 r0 top value=3.3nF
C81 "CC0603KRX5R6BB106" FP-CC0603KRX5R6BB106_0603-MFG 250.3,1334.86 r0 bottom value=10µF
C82 "885012205018" FP-885012205018_0402-MFG 249.99,1405.79 r180 bottom value=100nF
C83 "CC0603KRX5R6BB106" FP-CC0603KRX5R6BB106_0603-MFG 2079,1341.01 r180 bottom value=10µF
C84 "885012205018" FP-885012205018_0402-MFG 2071,1406 r0 bottom value=100nF
C85 "885012106018" 0603 1608.79,5011 r270 bottom value=2.2uF
C86 "885012205037" 0402 1149.95,3313.39 r90 bottom value=0.1uF
C87 "CGA2B3X7R1H104K050BB" 0402 1719.18,1017 r90 bottom value=0.1uF
C88 "GRM155R61E105KE11D" 0402 1666.99,1017 r90 bottom value=1uF
C89 "C1005X5R1V225K050BC" 0402_065 1465.98,1168.75 r270 bottom value=2.2uF
C90 "885012205037" 0402 1515.72,1168.75 r270 bottom value=0.1uF
C91 "885012005053" FP-885012005053_0402-MFG 1690.87,1103.94 r0 bottom value=4.7pF
C92 "885012005053" FP-885012005053_0402-MFG 1691.22,1134.36 r0 top value=4.7pF
C93 "885012005053" FP-885012005053_0402-MFG 1535.23,1143.35 r180 top value=4.7pF
C94 "885012005053" FP-885012005053_0402-MFG 1622.61,1162.77 r0 bottom value=4.7pF
C95 "CGA2B3X7R1H104K050BB" 0402 1612.99,1017 r90 bottom value=0.1uF
C96 "GRM155R61E105KE11D" 0402 1560.99,1017 r90 bottom value=1uF
C97 "GRM188R61A226ME15D" 0603 1604.23,1291.13 r0 bottom value=22uF
C98 "885012205037" 0402 1639.54,1234.67 r0 bottom value=0.1uF
C99 "GRM188R60J476ME15D" 0603 1633.17,1586.35 r90 top value=47uF
C100 "885012205037" 0402 1719.11,1560.38 r0 top value=0.1uF
C101 "GRM155R71H103KA88D" 0402 1959.32,344 r180 top value=0.01uF
C102 "CGA2B3X7R1H104K050BB" 0402 852,1017 r90 bottom value=0.1uF
C103 "885012205037" 0402 1152,719 r0 top value=0.1uF
C104 "GRM155R61E105KE11D" 0402 799.42,1017 r90 bottom value=1uF
C105 "C1005X5R1V225K050BC" 0402_065 617,1168.35 r270 bottom value=2.2uF
C106 "885012205037" 0402 666,1168.35 r270 bottom value=0.1uF
C107 "885012005053" FP-885012005053_0402-MFG 832.64,1144.96 r90 bottom value=4.7pF
C108 "885012005053" FP-885012005053_0402-MFG 832.1,1129.36 r0 top value=4.7pF
C109 "885012005053" FP-885012005053_0402-MFG 682.98,1134.36 r180 top value=4.7pF
C110 "885012005053" FP-885012005053_0402-MFG 768.34,1169.35 r0 bottom value=4.7pF
C111 "CGA2B3X7R1H104K050BB" 0402 747,1017 r90 bottom value=0.1uF
C112 "GRM155R61E105KE11D" 0402 695,1017 r90 bottom value=1uF
C113 "GRM188R61A226ME15D" 0603 740.15,1291.13 r0 bottom value=22uF
C114 "885012205037" 0402 782.47,1234.83 r180 bottom value=0.1uF
C115 "GRM188R60J476ME15D" 0603 779.1,1598.58 r90 top value=47uF
C116 "885012205037" 0402 865.95,1562.72 r180 top value=0.1uF
C117 "GRM155R71H103KA88D" 0402 341,343.81 r0 top value=0.01uF
C118 "GRM188R61C106KAALD" 0603 1395.51,4947.37 r90 bottom value=10uF
C119 "885012106018" 0603 221,3177 r180 bottom value=2.2uF
C120 "GRM188R61C106KAALD" 0603 338.6,3280.39 r270 top value=10uF
C121 "GRM188R61C106KAALD" 0603 158.49,5481 r90 bottom value=10uF
C122 "GRM188R61C106KAALD" 0603 538.77,5462.3 r90 bottom value=10uF
C123 "GRM155R61A102KA01D" 0402 428.99,5375.49 r0 bottom value=1000pF
C124 "885012205037" 0402 1949.99,3937.15 r90 top value=0.1uF
C125 "885012205037" 0402 1980.51,3760.31 r270 bottom value=0.1uF
C126 "0402ZD106MAT2A" 0402_080 865.81,6263.38 r270 top value=10uF
C127 "0402ZD106MAT2A" 0402_080 622.95,6331.51 r90 top value=10uF
C128 "885012205037" 0402 657.67,6197.8 r270 top value=0.1uF
C129 "885012205037" 0402 861.11,6058.14 r0 top value=0.1uF
C130 "885012205037" 0402 951.57,5651.26 r270 bottom value=0.1uF
C131 "885012205050" FP-885012205050_0402-MFG 2091.01,6549.5 r180 top value=10nF
C132 "885012205037" 0402 1249.95,5989.93 r180 bottom value=0.1uF
C133 "885012205037" 0402 1218,5635 r270 bottom value=0.1uF
C134 "885012205050" FP-885012205050_0402-MFG 1733.74,6516.54 r90 bottom value=10nF
C135 "885012205050" FP-885012205050_0402-MFG 1539.99,6520.75 r90 bottom value=10nF
C136 "885012205050" FP-885012205050_0402-MFG 1766.08,6015.27 r180 bottom value=10nF
C137 "885012205018" FP-885012205018_0402-MFG 1685.99,6015.27 r180 bottom value=100nF
C138 "885012205018" FP-885012205018_0402-MFG 1470.58,6134.64 r180 bottom value=100nF
C139 "885012105012" 0402 1938.49,6289.07 r90 bottom value=1uF
C140 "885012105012" 0402 1483.97,6431.06 r0 bottom value=1uF
C141 "885012205050" FP-885012205050_0402-MFG 1480.26,6381.33 r180 bottom value=10nF
C142 "885012105012" 0402 1938.48,6385.52 r270 bottom value=1uF
C143 "885012205018" FP-885012205018_0402-MFG 1666.29,6514.86 r90 bottom value=100nF
C144 "885012105012" 0402 1604.32,6505.81 r270 bottom value=1uF
C145 "885012205018" FP-885012205018_0402-MFG 2014.59,6077.67 r90 bottom value=100nF
C146 "CL05C120JB5NNNC" 0402 2091.29,6469.01 r90 top value=12pF
C147 "CL05C120JB5NNNC" 0402 2091.91,6364.67 r270 top value=12pF
"CE Logo1" "CE Mark" CE_Mark_5mm 542,474.07 r180 bottom
D11 "150080SS75000" WL-SMCW_RED_0805 2183.31,322.85 r180 top value=Red
D12 "150080VS75000" WL-SMCW_Green_0805 2182.31,230.08 r180 top value="Bright Green"
FID1 "Fiducial" Fiducial10-20 2064,73 r180 bottom
FID2 "Fiducial" Fiducial10-20 147.24,6442.18 r180 bottom
FID3 "Fiducial" Fiducial10-20 147.73,6443.34 r0 top
FID4 "Fiducial" Fiducial10-20 2064.52,73.29 r0 top
FID5 "Fiducial" Fiducial10-20 229.33,72.32 r180 bottom
FID6 "Fiducial" Fiducial10-20 228.03,72 r0 top
J1/J3 "SSQ-110-03-T-D" BoosterPack_40pin_J1J3 299.99,4824.64 r180 bottom locked
J4/J2 "SSQ-110-03-T-D" BoosterPack_40pin_J2J4 1999.99,4824.64 r180 bottom locked
J5/J7 "SSQ-110-03-T-D" BoosterPack_40pin_J5J7 299.99,2324.64 r180 bottom locked
J8/J6 "SSQ-110-03-T-D" BoosterPack_40pin_J6J8 1999.99,2324.64 r180 bottom locked
J10 "61300621121" Wurth_61300621121 299.99,3674.64 r0 top
J11 "61301021121" WURTH_61301021121 1999.99,3274.64 r270 top locked
J12 "61300511121" Wurth_61300511121 90.6,465.65 r90 top
J13 "61300511121" Wurth_61300511121 97.33,1060.05 r90 top
J14 "61300311121" WURTH_61300311121 2188.29,584.07 r270 top
J15 "61300211121" WURTH_61300211121#1 623.14,3907.14 r180 top
J16 "61300211121" WURTH_61300211121#2 249.99,5499.64 r90 top
J17 "61300211121" WURTH_61300211121#2 249.99,3324.64 r90 top
J101 "FTSH-107-01-F-DV-K" FP-FTSH-107-01-F-DV-K_HDR14-MFG 1538.46,5559.6 r180 top
JP1 "TSM-102-01-L-DV" Samtec_TSM-102-01-x-DV 235.61,5795 r270 top
JP4 "61300411121" WURTH_61300411121 2049.99,4024.64 r90 top
JP5 "61300311121" WURTH_61300311121 249.99,4074.64 r90 top locked
JP6 "61300311121" WURTH_61300311121 2049.99,1574.64 r90 top locked
JP7 "61300311121" WURTH_61300311121 249.99,1574.64 r90 top locked
JP8 "61300421121" FP-61300421121_HDR4-MFG 299.99,3024.64 r270 top locked
JP9 "61300211121" WURTH_61300211121#1 2137.99,829.31 r0 top
L1 "BLM21PG221SN1D" 0805_HV 1021.45,4144.7 r315 bottom value="220 ohm"
L2 "60 ohm" 0805_HV 667.14,3575.24 r0 bottom
L3 "60 ohm" 0805_HV 1073.29,3563.08 r45 bottom
L4 "LQM21PN1R0MC0D" 0805_HV 386,3435 r180 top value=1uH
LED1 "150080SS75000" WL-SMCW_RED_0805 244.09,6159.76 r0 top value=Red
LED3 "150080VS75000" WL-SMCW_Green_0805 472.46,3320.72 r90 top value="Bright Green"
LED4 "150080SS75000" WL-SMCW_RED_0805 1482.15,4589.81 r90 top value=Red
LED5 "LTST-C171GKT" LED_LTST-C171 1568.2,4583.11 r270 top value=Green
LED6 "150080VS75000" WL-SMCW_Green_0805 645.34,5436.73 r90 top value="Bright Green"
LED7 "150080SS75000" WL-SMCW_RED_0805 1012.37,6269.38 r180 top value=Red
LED8 "LTST-C170TBKT" LTST-C170TBKT_Blue 1282.24,6615 r90 top value=Blue
LED9 "LTST-C170TBKT" LTST-C170TBKT_Blue 1197.99,6614.64 r90 top value=Blue
Logo1 "Texas Instruments" TI_Stacked_Overlay_Medium 1167.12,4708.78 r180 bottom
Logo3 "FCC disclaimer" FCC_disclaimer 2881,-1914 r180 bottom
Logo4 "WEEE logo" WEEE_Minimum 801.93,519.78 r180 bottom
Logo5 "Texas Instruments" TI_Symbol_Overlay_Small 1010.82,6604.64 r0 top
Logo6 "ETHERCAT LABEL" EtherCAT_label 693.7,4061.58 r0 top
M1 "60900213421" Wurth_60900213421 344.93,3036.18 r270 top
M2 "60900213421" Wurth_60900213421 254.99,3036.04 r90 top
M3 "60900213421" Wurth_60900213421 244.93,5498.8 r90 top
M4 "60900213421" Wurth_60900213421 2142.49,820 r180 top
M5 "60900213421" Wurth_60900213421 622.76,3904.37 r180 top
M6 "60900213421" Wurth_60900213421 288.93,5807 r90 top
M7 "60900213421" Wurth_60900213421 187.5,5806 r90 top
MH1 "MTG_NoPads" NPTH125mil#1 99.99,6649.64 r0 top
MH2 "MTG_NoPads" NPTH125mil#1 2199.99,6649.64 r0 top
MH3 "MTG_NoPads" NPTH125mil#2 99.99,1349.64 r0 top
MH4 "MTG_NoPads" NPTH125mil#2 2199.99,1349.64 r0 top locked
R1 "ERJ-3GEY0R00V" 0603 1825.11,5271.89 r180 top value=0
R2 "ERJ-3GEY0R00V" 0603 1825.96,5158.98 r180 top value=0
R3 "ERJ-3GEY0R00V" 0603 1826.5,2767.89 r180 top value=0
R4 "ERJ-3GEY0R00V" 0603 1827.51,2655 r180 top value=0
R5 "CRCW04021K00FKED" 0402 178.35,260 r270 top value=1.00k
R6 "CRCW04021K00FKED" 0402 239.63,437.1 r270 top value=1.00k
R7 "CRCW04021K00FKED" 0402 239.63,542.43 r270 top value=1.00k
R8 "CRCW04021K00FKED" 0402 241.65,834 r270 top value=1.00k
R9 "CRCW04021K00FKED" 0402 241.81,938 r270 top value=1.00k
R10 "CRCW04021K00FKED" 0402 242.31,1043.05 r270 top value=1.00k
R11 "RC0603FR-07120RL" 0603 2171.49,934.65 r0 top value=120
R12 "CRCW0402680RJNED" 0402 1403.55,4543.15 r270 top value=680
R13 "CRCW0402680RJNED" 0402 1643.45,4560.56 r270 top value=680
R14 "CRCW040210M0JNED" 0402 1403.55,4434.14 r90 top value=10Meg
R15 "CRCW040210M0JNED" 0402 1643.14,4452.76 r90 top value=10Meg
R16 "CRCW04023K30JNED" 0402 1609.46,5902.6 r270 top value=3.3k
R17 "CRCW06030000Z0EA" 0603 1495.63,4257.11 r90 top value=0
R18 "RC0402JR-070RL" 0402 537.59,4359.81 r0 top value=0
R19 "CRCW06030000Z0EA" 0603 1560.53,4257.11 r90 top value=0
R20 "CPF0402B10RE1" CPF0402 1595.83,3420.7 r90 top value=10.0
R21 "CPF0402B10RE1" CPF0402 1265.92,3038.23 r270 top value=10.0
R22 "CPF0402B10RE1" CPF0402 1314.54,3037.98 r270 top value=10.0
R23 "CRCW04020000Z0EDHP" 0402 1564.32,3124.77 r180 top value=0
R24 "CRCW04020000Z0EDHP" 0402 1641.48,3370.36 r180 bottom value=0
R25 "ERJ-3GEY0R00V" 0603 1164.74,1090.02 r180 top value=0
R26 "CRCW04020000Z0EDHP" 0402 1496.77,3370.36 r0 bottom value=0
R27 "ERJ-3GEY0R00V" 0603 1164.74,1215.02 r180 top value=0
R28 "ERJ-3GEY0R00V" 0603 1164.74,1027.02 r0 top value=0
R29 "ERJ-3GEY0R00V" 0603 1164.74,1152.02 r0 top value=0
R30 "CRCW06030000Z0EA" 0603 1287.4,2004.39 r0 top value=0
R31 "RC0603FR-0710KL" 0603 811.41,4361.28 r0 bottom value=10.0k
R32 "CRCW04024K70JNED" 0402 1374.33,1237.44 r90 top value=4.7k
R33 "RC0603FR-0710KL" 0603 1176.12,4361.28 r0 bottom value=10.0k
R34 "CRCW06032K20JNEA" 0603 1286.97,1940.4 r0 top value=2.2k
R35 "CRCW06030000Z0EA" 0603 1287.4,2067.99 r180 top value=0
R36 "CRCW06030000Z0EA" 0603 1286.97,1876.4 r0 top value=0
R37 "CRCW06030000Z0EA" 0603 1391.77,2345.19 r90 bottom value=0
R38 "RC0402JR-070RL" 0402 537.59,4939.12 r0 top value=0
R39 "RC0402JR-070RL" 0402 542,2603.44 r0 top value=0
R40 "RC0402JR-070RL" 0402 537.59,4608.08 r0 top value=0
R41 "RC0402JR-070RL" 0402 537.59,2435.35 r0 top value=0
R42 "RC0402JR-070RL" 0402 537.59,2099.15 r0 top value=0
R43 "RC0402JR-070RL" 0402 537.59,5104.64 r0 top value=0
R44 "CRCW04022K20JNED" 0402 981.13,3525.99 r225 top value=2.2k
R45 "RC0402JR-070RL" 0402 537.59,2519.39 r0 top value=0
R46 "RC0402JR-070RL" 0402 537.59,5021.88 r0 top value=0
R47 "ERJ-3GEY0R00V" 0603 1804.55,4046.08 r0 bottom value=0
R48 "RC0402JR-070RL" 0402 541,1847 r0 top value=0
R49 "RC0402JR-070RL" 0402 537.59,2351.3 r0 top value=0
R50 "RC0402JR-070RL" 0402 537.59,4856.36 r0 top value=0
R51 "RC0402JR-070RL" 0402 537.59,2015.1 r0 top value=0
R52 "RC0402JR-070RL" 0402 537.59,4525.32 r0 top value=0
R53 "ERJ-3GEY0R00V" 0603 1804.55,4108.08 r180 bottom value=0
R54 "RC0402JR-070RL" 0402 457.63,3748.62 r0 top value=0
R55 "RC0402JR-070RL" 0402 457.63,3699.87 r0 top value=0
R56 "RC0402JR-070RL" 0402 537.59,4690.84 r0 top value=0
R57 "RC0402JR-070RL" 0402 537.59,2183.2 r0 top value=0
R58 "CRCW04020000Z0EDHP" 0402 1482.44,1625.08 r90 bottom value=0
R59 "CRCW04022K20JNED" 0402 2017.76,3618.79 r90 bottom value=2.2k
R60 "RC0402JR-070RL" 0402 537.59,4773.6 r0 top value=0
R61 "RC0402JR-070RL" 0402 537.59,2267.25 r0 top value=0
R62 "RC0402JR-070RL" 0402 537.59,1931.05 r0 top value=0
R63 "RC0402JR-070RL" 0402 537.59,4442.57 r0 top value=0
R64 "RC0402JR-070RL" 0402 457.63,3748.62 r0 bottom value=0
R65 "RC0402JR-070RL" 0402 457.63,3699.87 r0 bottom value=0
R66 "ERJ3LWFR005V" 0603 423.52,4034.01 r270 top value=0.005
R67 "RG1608P-124-B-T5" 0603 521.25,4241.58 r180 top value=120k
R68 "CRCW04021M00FKED" 0402 374.99,6377.46 r0 top value=1.00Meg
R69 "RC0603JR-073KL" 0603 242.13,6240.51 r180 top value=3.0k
R70 "ERJ-3GEY0R00V" 0603 1458.73,4947.64 r90 bottom value=0
R72 "CRCW040213K0FKED" 0402 1414.36,5030.23 r0 top value=13.0k
R74 "ERJ-3GEY0R00V" 0603 839.18,5647.36 r270 bottom value=0
R76 "ERJ-3GEY0R00V" 0603 1275.09,5648 r270 bottom value=0
R78 "RC0603JR-075K1L" 0603 400.37,6199.13 r90 top value=5.1k
R79 "CRCW040211K0FKED" 0402 1426.18,4974.86 r0 top value=11.0k
R81 "RC0603JR-075K1L" 0603 462.87,6199.13 r90 top value=5.1k
R82 "CRCW04021K10JNED" 0402 404.01,3331.57 r270 top value=1.1k
R83 "CRCW04020000Z0EDHP" 0402 1378.72,1451.08 r180 bottom value=0
R84 "CRCW04020000Z0EDHP" 0402 1378.72,1500.15 r180 bottom value=0
R85 "CRCW04024K99FKED" 0402 527.58,5395.27 r270 top value=4.99k
R86 "CRCW04020000Z0EDHP" 0402 1378.72,1548.91 r180 bottom value=0
R87 "CRCW04020000Z0EDHP" 0402 1432.06,1625.84 r90 bottom value=0
R88 "CRCW04022K49FKED" 0402 1573.17,1597.46 r270 top value=2.49k
R89 "CRCW04022K49FKED" 0402 1828.75,1395 r0 top value=2.49k
R90 "CRCW0402680RJNED" 0402 576.92,5395.27 r90 top value=680
R91 "CRCW04020000Z0EDHP" 0402 618.85,1620.23 r90 bottom value=0
R92 "CRCW04020000Z0EDHP" 0402 515.74,1445.51 r180 bottom value=0
R94 "CRCW04021K21FKED" 0402 527.12,5501.96 r270 top value=1.21k
R95 "ERJ-3GEY0R00V" 0603 1938.83,3618.79 r90 bottom value=0
R96 "CRCW0402680RJNED" 0402 914.88,6263.38 r270 top value=680
R97 "ERJ-3GEY0R00V" 0603 758.11,5647.5 r90 bottom value=0
R98 "ERJ-3GEY0R00V" 0603 695.11,5647.5 r90 bottom value=0
R99 "ERJ-3GEY0R00V" 0603 632.11,5647.5 r90 bottom value=0
R100 "ERJ-3GEY0R00V" 0603 569.11,5647.5 r90 bottom value=0
R101 "CRCW04021K00FKED" 0402 2014.18,5926.74 r0 top value=1.00k
R102 "CRCW04021K00FKED" 0402 2014.18,5876.99 r0 top value=1.00k
R103 "CRCW04021K00FKED" 0402 1881.73,5904.66 r270 top value=1.00k
R104 "CRCW04021K00FKED" 0402 1832.59,5904.36 r270 top value=1.00k
R105 "CRCW04024K70JNED" 0402 1237.19,3187.09 r0 top value=4.7k
R106 "CRCW04024K70JNED" 0402 1237.41,3237.5 r0 top value=4.7k
R107 "CRCW04022K20FKED" 0402 1794,1331.41 r0 bottom value=2.20k
R108 "CRCW04024K70JNED" 0402 1580.66,1625.01 r90 bottom value=4.7k
R109 "CRCW04026K49FKED" 0402 1794,1274.32 r180 bottom value=6.49k
R110 "CRCW04020000Z0EDHP" 0402 515.3,1494.37 r180 bottom value=0
R111 "CRCW04022K49FKED" 0402 1828.75,1446 r0 top value=2.49k
R112 "CRCW04022K49FKED" 0402 1522.97,1596.75 r90 top value=2.49k
R113 "CRCW04022K49FKED" 0402 1828.75,1502 r0 top value=2.49k
R114 "CRCW040233R2FKED" 0402 1678.42,1624.74 r270 bottom value=33.2
R115 "CRCW040233R2FKED" 0402 1726.85,1625.09 r270 bottom value=33.2
R116 "CRCW040233R2FKED" 0402 1794,1502.69 r180 bottom value=33.2
R117 "CRCW040233R2FKED" 0402 1794,1445.6 r180 bottom value=33.2
R118 "CRCW040233R2FKED" 0402 1794,1388.5 r180 bottom value=33.2
R119 "CRCW040233R2FKED" 0402 1629.28,1625.44 r270 bottom value=33.2
R120 "CRCW040233R2FKED" 0402 1531.6,1625.15 r270 bottom value=33.2
R121 "CRCW040233R2FKED" 0402 1378.72,1402.08 r0 bottom value=33.2
R122 "CRCW040233R2FKED" 0402 1378.72,1352.41 r0 bottom value=33.2
R123 "CRCW04022K20FKED" 0402 1326.23,1274.05 r90 bottom value=2.20k
R124 "CRCW04022K20FKED" 0402 1374.77,1274.05 r90 bottom value=2.20k
R125 "CRCW04022K20FKED" 0402 1423.6,1274.05 r90 bottom value=2.20k
R126 "CRCW040233R2FKED" 0402 1792.32,1559.78 r180 bottom value=33.2
R127 "CRCW04022K49FKED" 0402 1719.13,1611.56 r180 top value=2.49k
R128 "CRCW04022K49FKED" 0402 1828.75,1548 r180 top value=2.49k
R129 "CRCW04022K49FKED" 0402 1428.56,1274.65 r90 top value=2.49k
R130 "CRCW04022K49FKED" 0402 723.22,1609.31 r270 top value=2.49k
R131 "RMCF0402ZT0R00" "FP-RMCF0402ZT0R00_0402 (1005 metric)-0" 1690.46,1186.82 r180 bottom
R132 "CRCW0603470RJNEA" 0603 1422.64,1128.4 r180 top value=470
R133 "CRCW04022K49FKED" 0402 991.21,1399.57 r0 top value=2.49k
R134 "RMCF0402ZT0R00" "FP-RMCF0402ZT0R00_0402 (1005 metric)-0" 1719.87,1517.82 r0 top
R135 "CRCW0603470RJNEA" 0603 1797.04,1184.73 r270 top value=470
R136 "RMCF0402FT1M00" 0402 1959.32,293 r180 top value=1.00Meg
R137 "CRCW04021K27FKED" 0402 1959.48,448.55 r180 top value=1.27k
R138 "CRCW0402680RJNED" 0402 1959.32,396.16 r0 top value=680
R139 "CRCW04021M50JNED" 0402 1114.84,415 r270 top value=1.5Meg
R140 "CRCW04021M50JNED" 0402 1185.06,415 r270 top value=1.5Meg
R141 "CRCW04024K70JNED" 0402 549.21,1245.25 r0 top value=4.7k
R142 "CRCW04024K70JNED" 0402 717.94,1620.23 r90 bottom value=4.7k
R143 "CRCW04026K49FKED" 0402 942,1351.19 r180 bottom value=6.49k
R144 "CRCW04020000Z0EDHP" 0402 516.12,1542.86 r180 bottom value=0
R145 "CRCW04022K49FKED" 0402 991.21,1448.42 r0 top value=2.49k
R146 "CRCW04022K49FKED" 0402 673.15,1609.31 r90 top value=2.49k
R147 "CRCW04022K49FKED" 0402 991.21,1497.27 r180 top value=2.49k
R148 "CRCW040233R2FKED" 0402 816.71,1620.23 r270 bottom value=33.2
R149 "CRCW040233R2FKED" 0402 865.45,1620.23 r270 bottom value=33.2
R150 "CRCW040233R2FKED" 0402 942,1497.38 r180 bottom value=33.2
R151 "CRCW04022K20FKED" 0402 579,1273.22 r270 bottom value=2.20k
R152 "CRCW040233R2FKED" 0402 942,1448.97 r180 bottom value=33.2
R153 "CRCW040233R2FKED" 0402 942,1399.57 r180 bottom value=33.2
R154 "CRCW040233R2FKED" 0402 767.33,1620.23 r270 bottom value=33.2
R155 "CRCW040233R2FKED" 0402 668.56,1620.23 r270 bottom value=33.2
R156 "CRCW040233R2FKED" 0402 516.31,1397.27 r0 bottom value=33.2
R157 "CRCW040233R2FKED" 0402 517,1349 r0 bottom value=33.2
R158 "CRCW040233R2FKED" 0402 942,1546.11 r180 bottom value=33.2
R159 "CRCW04022K20FKED" 0402 481,1273.22 r90 bottom value=2.20k
R160 "CRCW04022K20FKED" 0402 530,1273.22 r90 bottom value=2.20k
R161 "CRCW04022K49FKED" 0402 865.48,1612.97 r180 top value=2.49k
R162 "CRCW04022K49FKED" 0402 991.21,1546.11 r180 top value=2.49k
R163 "CRCW04022K49FKED" 0402 550.5,1298.22 r180 top value=2.49k
R164 "CRCW0402100RJNED" 0402 2024.59,6615 r270 top value=100
R165 "ERJ-3GEY0R00V" 0603 1131.89,5651.26 r90 bottom value=0
R166 "RMCF0402ZT0R00" "FP-RMCF0402ZT0R00_0402 (1005 metric)-0" 849.73,1191.4 r180 bottom
R167 "CRCW0603470RJNEA" 0603 562.54,1129.58 r180 top value=470
R168 "RMCF0402ZT0R00" "FP-RMCF0402ZT0R00_0402 (1005 metric)-0" 859.89,1510.09 r0 top
R169 "CRCW0603470RJNEA" 0603 936.93,1205.15 r270 top value=470
R170 "RMCF0402FT1M00" 0402 341,289.81 r0 top value=1.00Meg
R171 "ERJ-3GEY0R00V" 0603 1068.17,5651.26 r90 bottom value=0
R172 "RC0402FR-07470RL" 0402 1280.25,6486.36 r270 top value=470
R173 "RC0402FR-07470RL" 0402 1197.5,6487.17 r270 top value=470
R174 "CRCW040210K0JNED" 0402 2092.28,6111.26 r270 top value=10k
R175 "CRCW040210K0JNED" 0402 2092.28,6216.52 r270 top value=10k
R176 "CRCW04024K87FKED" 0402 1783.34,5904.22 r90 top value=4.87k
R177 "CRCW040251R0JNED" 0402 2092.28,6006 r90 top value=51
R203 "CRCW04020000Z0EDHP" 0402 568.95,1620.23 r90 bottom value=0
RJ1 "7498010210A" Wurth_7498010210A 1580.56,162 r270 top locked
RJ2 "7498010210A" Wurth_7498010210A 718.84,162 r270 top locked
S1 "1188E-1K2-V-TR" SW_1188E 2179.99,5524.64 r180 top
S2 "CAS-D20TA" SW_CAS-D20TA 1050.8,5004.64 r0 top
S3 "CAS-D20TA" SW_CAS-D20TA 1050.8,4361.28 r180 top
S4 "CAS-220TA" SW_CAS-220TA 1586.62,1983.19 r180 top
S5 "CAS-D20TA" SW_CAS-D20TA 1205.41,2679.53 r180 top
TP1 "TESTPOINT" TP_50MIL-25MILHOLE#1 382.81,4153.47 r0 top
TP2 "TESTPOINT" TP_50MIL-25MILHOLE#2 332.5,3877.37 r0 top
TP3 "TESTPOINT" TP_50MIL-25MILHOLE#3 811.41,3824.97 r0 top
TP4 "TESTPOINT" TP_50MIL-25MILHOLE#3 1333.3,1803.79 r0 top
TP5 "TESTPOINT" TP_50MIL-25MILHOLE#3 64.49,1764.2 r0 top
TP6 "TESTPOINT" TP_50MIL-25MILHOLE#3 2049.68,2975.27 r0 top
TP7 "TESTPOINT" TP_50MIL-25MILHOLE#3 1902.49,1727.23 r90 top
TP8 "TESTPOINT" TP_50MIL-25MILHOLE#3 1902.49,1662 r90 top
U1 "TMS320F28P650DK9NMR" NMR0169A-MFG 1149.95,3820.69 r315 top locked
U2 "MSP432E401YTPDT" PDT0128A 1700.19,6299.64 r0 top locked
U3 "REF6230IDGKR" DGK0008A_N 522.9,4088.75 r270 top
U4 "TPD4E004DRYR" DRY0006A 783.64,5515.98 r90 top
U5 "TPD4E004DRYR" DRY0006A 1088.9,5526.81 r90 top
U6 "TS5A23157DGSR" DGS0010A_N 839.74,5221.66 r0 top
U7 "SN74LVC2G07DBVR" DBV0006A_N 1529.55,4405.67 r90 top
U8 "TS5A23157DGSR" DGS0010A_N 1387,5221.66 r0 top
U9 "TS5A23157DGSR" DGS0010A_N 1138.18,5310.89 r90 top
U10 "TPS3703A4120DSERQ1" DSE0006A 1928,3855 r180 bottom
U11 "SN74LV4053APWR" PW0016A-MFG 1063.28,2326.49 r180 top
U12 "CAT24C16WI-GT3" SOIC-8 1042.18,3263.18 r0 top
U13 "SN74LVC8T245PW" PW0024A_N 1047.28,1947.76 r270 top
U14 "SN74LV4053APWR" PW0016A-MFG 1438.33,2326.49 r180 top
U15 "TCAN332DR" D0008A_N 2129.49,1130.31 r270 top
U16 "TPD4E05U06DQAR" DQA0010A#1 504.83,6361.93 r90 top
U17 "DP83826ERHB" RHB0032M 1600.99,1368.2 r90 top
U18 "SN74LVC2G06DBVR" DBV0006A_N 1150.22,587.85 r90 top
U19 "TPD4E05U06DQAR" DQA0010A#2 1620.99,1191 r270 top
U20 "DP83826ERHB" RHB0032M 736.84,1368.2 r90 top
U21 "TPD4E05U06DQAR" DQA0010A#2 755,1191 r270 top
U22 "TLV75901PDRVT" DRV0006A-MFG 1543.22,5004.64 r0 top
U23 "TPS61241YFFR" YFF0006AEAE 335.75,3364.87 r270 top
U24 "TPS7A7401DSDR" DSD0008B-MFG 410.74,5462.3 r0 top
U25 "TLV70333DBVR" DBV0005A-MFG 761.69,6264.39 r0 top
U26 "ISO7741DWR" DW0016B_HV 663.77,5798 r270 top locked
U27 "ISO7731DWR" DW0016B_HV 1101.45,5798 r270 top locked
USB1 "MUP-U22001" FP-MUP-U22001_CONN_USB_8MM94_8MM0-MFG 480.31,6610.67 r180 top locked
Y1 "NX3225GA-16.000M-STD-CRG-1" NDK_NX3225GA 2180.19,6409.64 r180 top
Y2 "LMK6CE02500CDLFT" DLF0004A-MFG 1566.19,3232.99 r90 top
ZZ1 "These assemblies are ESD sensitive, ESD precautions shall be observed." AssemblyNote 2.89,7497 r0 top
ZZ2 "These assemblies must be clean and free from flux and all contaminants. Use of no clean flux is not acceptable." AssemblyNote -0.01,7411 r0 top
ZZ3 "These assemblies must comply with workmanship standards IPC-A-610 Class 2, unless otherwise specified." AssemblyNote -0.01,7311 r0 top

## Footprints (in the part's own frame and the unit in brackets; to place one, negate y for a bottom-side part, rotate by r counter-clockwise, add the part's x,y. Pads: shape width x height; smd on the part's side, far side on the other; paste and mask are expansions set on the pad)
0402 [mm] "0402 from SM-752 data"
  rect 0.8x0.6 smd: 1(-0.6,0) 2(0.6,0)
  silkscreen extent -1.22,-0.52 1.22,0.52, body extent -0.55,-0.3 0.55,0.3, height 0.6
0402_065 [mm] "0402"
  rect 0.8x0.6 smd: 1(-0.6,0) 2(0.6,0)
  silkscreen extent -1.22,-0.52 1.22,0.52, body extent -0.55,-0.3 0.55,0.3, height 0.65
0402_080 [mm] "SMD, 2-Leads, Body 1x0.5mm"
  rect 0.8x0.6 smd: 1(-0.6,0) 2(0.6,0)
  silkscreen extent -1.22,-0.52 1.22,0.52, body extent -0.65,-0.4 0.65,0.4, height 0.8
0603 [mm] "0603 from SM-752 data"
  rect 1x0.95 smd: 1(-0.8,0) 2(0.8,0)
  silkscreen extent -1.52,-0.69 1.52,0.69, body extent -0.87,-0.47 0.87,0.47, height 1
0805_HV [mil] "0805 with 30mil clearance between pads"
  rect 50x63 smd: 1(-40,0) 2(40,0)
  silkscreen extent -74,-40 74,40, body extent -43,-29 43,29, height 57
AssemblyNote [mil] "Assembly Note"
BoosterPack_40pin_J1J3 [mm] "Receptacle, 2.54mm, 10x2, TH"
  rrect6% 1.55x1.55 hole 1.02: 1(1.27,11.43)
  round 1.55 hole 1.02: 2(1.27,8.89) 3(1.27,6.35) 4(1.27,3.81) 5(1.27,1.27) 6(1.27,-1.27) 7(1.27,-3.81) 8(1.27,-6.35) 9(1.27,-8.89) 10(1.27,-11.43) 21(-1.27,11.43) 22(-1.27,8.89) 23(-1.27,6.35) 24(-1.27,3.81) 25(-1.27,1.27) 26(-1.27,-1.27) 27(-1.27,-3.81) 28(-1.27,-6.35) 29(-1.27,-8.89) 30(-1.27,-11.43)
  silkscreen extent -7.62,-12.95 7.62,12.95, body extent 0,0 0,0
BoosterPack_40pin_J2J4 [mm] "Receptacle, 2.54mm, 10x2, TH"
  round 1.55 hole 1.02: 11(-1.27,-11.43) 12(-1.27,-8.89) 13(-1.27,-6.35) 14(-1.27,-3.81) 15(-1.27,-1.27) 16(-1.27,1.27) 17(-1.27,3.81) 18(-1.27,6.35) 19(-1.27,8.89) 20(-1.27,11.43) 31(1.27,-11.43) 32(1.27,-8.89) 33(1.27,-6.35) 34(1.27,-3.81) 35(1.27,-1.27) 36(1.27,1.27) 37(1.27,3.81) 38(1.27,6.35) 39(1.27,8.89) 40(1.27,11.43)
  silkscreen extent -7.62,-12.95 2.48,12.95, body extent 0,0 0,0
BoosterPack_40pin_J5J7 [mm] "Receptacle, 2.54mm, 10x2, TH"
  round 1.55 hole 1.02: 41(1.27,11.43) 42(1.27,8.89) 43(1.27,6.35) 44(1.27,3.81) 45(1.27,1.27) 46(1.27,-1.27) 47(1.27,-3.81) 48(1.27,-6.35) 49(1.27,-8.89) 50(1.27,-11.43) 61(-1.27,11.43) 62(-1.27,8.89) 63(-1.27,6.35) 64(-1.27,3.81) 65(-1.27,1.27) 66(-1.27,-1.27) 67(-1.27,-3.81) 68(-1.27,-6.35) 69(-1.27,-8.89) 70(-1.27,-11.43)
  silkscreen extent -7.62,-12.95 7.62,12.95, body extent 0,0 0,0
BoosterPack_40pin_J6J8 [mm] "Receptacle, 2.54mm, 10x2, TH"
  round 1.55 hole 1.02: 51(-1.27,-11.43) 52(-1.27,-8.89) 53(-1.27,-6.35) 54(-1.27,-3.81) 55(-1.27,-1.27) 56(-1.27,1.27) 57(-1.27,3.81) 58(-1.27,6.35) 59(-1.27,8.89) 60(-1.27,11.43) 71(1.27,-11.43) 72(1.27,-8.89) 73(1.27,-6.35) 74(1.27,-3.81) 75(1.27,-1.27) 76(1.27,1.27) 77(1.27,3.81) 78(1.27,6.35) 79(1.27,8.89) 80(1.27,11.43)
  silkscreen extent -7.62,-12.95 2.48,12.95, body extent 0,0 0,0
CE_Mark_5mm [mil] "Minimum text height for CE Mark"
  silkscreen extent -138,-98 138,98
CPF0402 [mm] "TE Connectivity"
  rect 0.5x0.6 smd: 1(-0.5,0) 2(0.5,0)
  silkscreen extent -0.97,-0.53 0.97,0.53, body extent -0.55,-0.27 0.55,0.27, height 0.35
D0008A_N [mm] "SOIC, 8-Leads, Body 4.9x3.9mm, Pitch 1.27mm, IPC Medium Density"
  oval 1.45x0.6 smd: 1(-2.725,1.905) 2(-2.725,0.635) 3(-2.725,-0.635) 4(-2.725,-1.905) 5(2.725,-1.905) 6(2.725,-0.635) 7(2.725,0.635) 8(2.725,1.905)
  silkscreen extent -3.3,-2.5 0.9,2.5, body extent -3,-2.45 3,2.45, height 1.63
DBV0005A-MFG [mm]
  rrect17% 1.1x0.6 smd paste+0 mask+0: 1(-1.3,0.95) 2(-1.3,0) 3(-1.3,-0.95) 4(1.3,-0.95) 5(1.3,0.95)
  silkscreen extent -2.57,-1.53 0.87,1.53, body extent -1.95,-1.78 1.95,1.78, height 0.25
DBV0006A_N [mm] "SOT23, 6-Leads, Body 2.9x1.6mm, Pitch 0.95mm, Lead Span 2.8mm, IPC Medium Density"
  rrect17% 1x0.6 smd: 1(-1.375,0.95) 2(-1.375,0) 3(-1.375,-0.95) 4(1.375,-0.95) 5(1.375,0) 6(1.375,0.95)
  silkscreen extent -1.67,-1.55 0.5,1.55, body extent -1.42,-1.46 1.42,1.46, height 1.12
DGK0008A_N [mm] "TSOP, 8-Leads, Body 3x3mm, Pitch 0.65mm, IPC Medium Density"
  oval 1.35x0.45 smd: 1(-2.225,0.975) 2(-2.225,0.325) 3(-2.225,-0.325) 4(-2.225,-0.975) 5(2.225,-0.975) 6(2.225,-0.325) 7(2.225,0.325) 8(2.225,0.975)
  silkscreen extent -2.75,-1.55 0.95,1.55, body extent -2.45,-1.5 2.45,1.5, height 0.96
DGS0010A_N [mm] "TSSOP, 10-Leads, Body 3x3mm, Pitch 0.5mm, IPC Medium Density"
  oval 1.35x0.3 smd: 1(-2.225,1) 2(-2.225,0.5) 3(-2.225,0) 4(-2.225,-0.5) 5(-2.225,-1) 6(2.225,-1) 7(2.225,-0.5) 8(2.225,0) 9(2.225,0.5) 10(2.225,1)
  silkscreen extent -2.75,-1.55 0.9,1.55, body extent -2.45,-1.5 2.45,1.5, height 0.96
DLF0004A-MFG [mm]
  rrect15% 0.9x0.65 smd paste-1000 mask+0: 1(-0.75,0.825) 2(-0.75,-0.825) 3(0.75,-0.825) 4(0.75,0.825)
  silkscreen extent -1.87,-0.13 1.05,0.95, body extent -1,-1.25 1,1.25, height 1
DQA0010A#1 [mm] "SON, 10-Leads, Body 1x2.5mm, Pitch 0.5mm, TI Recommended"
  rrect50% 0.565x0.2 smd: 1(-0.417,1) 2(-0.418,0.5) 4(-0.418,-0.5) 5(-0.418,-1) 6(0.417,-1) 7(0.417,-0.5) 9(0.417,0.5) 10(0.417,1)
  rrect25% 0.565x0.4 smd: 3(-0.418,0) 8(0.417,0)
  rrect28% 0.565x0.36 on Top Paste: 3(-0.418,0) 8(0.417,0)
  silkscreen extent -0.67,-1.45 0.55,1.45, body extent -0.55,-1.3 0.55,1.3, height 0.56
DQA0010A#2 [mm] "SON, 10-Leads, Body 1x2.5mm, Pitch 0.5mm, TI Recommended"
  rrect50% 0.565x0.2 smd: 1(-0.417,1) 2(-0.417,0.5) 4(-0.417,-0.5) 5(-0.417,-1) 6(0.417,-1) 7(0.417,-0.5) 9(0.417,0.5) 10(0.417,1)
  rrect28% 0.565x0.36 on Top Paste: 3(-0.417,0) 8(0.417,0)
  rrect25% 0.565x0.4 smd paste-0.2: 3(-0.417,0) 8(0.417,0)
  silkscreen extent -0.67,-1.45 0.55,1.45, body extent -0.55,-1.3 0.55,1.3, height 0.56
DRV0006A-MFG [mm]
  rrect33% 0.45x0.3 smd paste+0 mask+0: 1(-0.975,0.65) 2(-0.975,0) 3(-0.975,-0.65) 4(0.975,-0.65) 5(0.975,0) 6(0.975,0.65)
  rrect10% 1x1.6 smd paste-1000 mask+0: 7(0,0)
  silkscreen extent -1.87,-1.17 1.05,1.17, body extent -1.3,-1.15 1.3,1.15, height 0.25
DRY0006A [mm] "USON-6"
  rrect67% 0.45x0.3 smd: 1(-0.275,0.5)
  rrect67% 0.4x0.3 smd: 2(-0.3,0) 3(-0.3,-0.5) 4(0.3,-0.5) 5(0.3,0) 6(0.3,0.5)
  body extent -0.5,-0.72 0.5,0.73, height 0.58
DSD0008B-MFG [mm]
  rrect32% 0.6x0.31 smd paste+0 mask+0: 1(-1.4,0.975) 2(-1.4,0.325) 3(-1.4,-0.325) 4(-1.4,-0.975) 5(1.4,-0.975) 6(1.4,-0.325) 7(1.4,0.325) 8(1.4,0.975)
  rrect6% 1.65x2.4 smd paste-1000 mask+0: 9(0,0)
  silkscreen extent -2.27,-1.59 1.55,1.59, body extent -1.8,-1.65 1.8,1.65, height 0.25
DSE0006A [mm] "TI recommended land pattern"
  rect 0.66x0.25 smd: 1(-0.62,0.5)
  rect 0.7x0.25 smd: 2(-0.6,0) 3(-0.6,-0.5) 4(0.6,-0.5) 5(0.6,0) 6(0.6,0.5)
  Top Signal region: -0.3,0.625 -0.25,0.625 -0.15,0.525 -0.15,0.375 -0.3,0.375
  silkscreen extent -0.9,-0.92 0.9,0.92, body extent -0.77,-0.77 0.77,0.77, height 0.8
